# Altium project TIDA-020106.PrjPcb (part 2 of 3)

## Sheet CAN.SchDoc: CAN
size A4; Date: Not shown in title block; ApprovedBy: Hely Zhang; CheckedBy: Not shown in title block; Author: Not shown in title block; CompanyName: Not shown in title block; DrawnBy: Hely Zhang; Engineer: Not shown in title block; Organization: Not shown in title block; Address1: Not shown in title block; Address2: Not shown in title block; Address3: Not shown in title block; Address4: Not shown in title block; DocumentNumber: 1; Revision: Use project parameter SCH_Rev; SheetNumber: 8; SheetTotal: 15; PageSetup: Record=PageOptions¦CenterHorizontal=True¦CenterVertical=True¦PrintScale=0.93¦XCorrection=1.00¦YCorrection=1.00¦PrintKind=0¦BorderSize=5000000¦LeftOffset=0¦BottomOffset=0¦Orientation=2¦PaperLength=1000¦PaperWidth=1000¦Scale=100¦PaperSource=15¦PrintQuality=600¦MediaType=1¦DitherType=10¦PaperKind=Letter¦PrintScaleMode=1
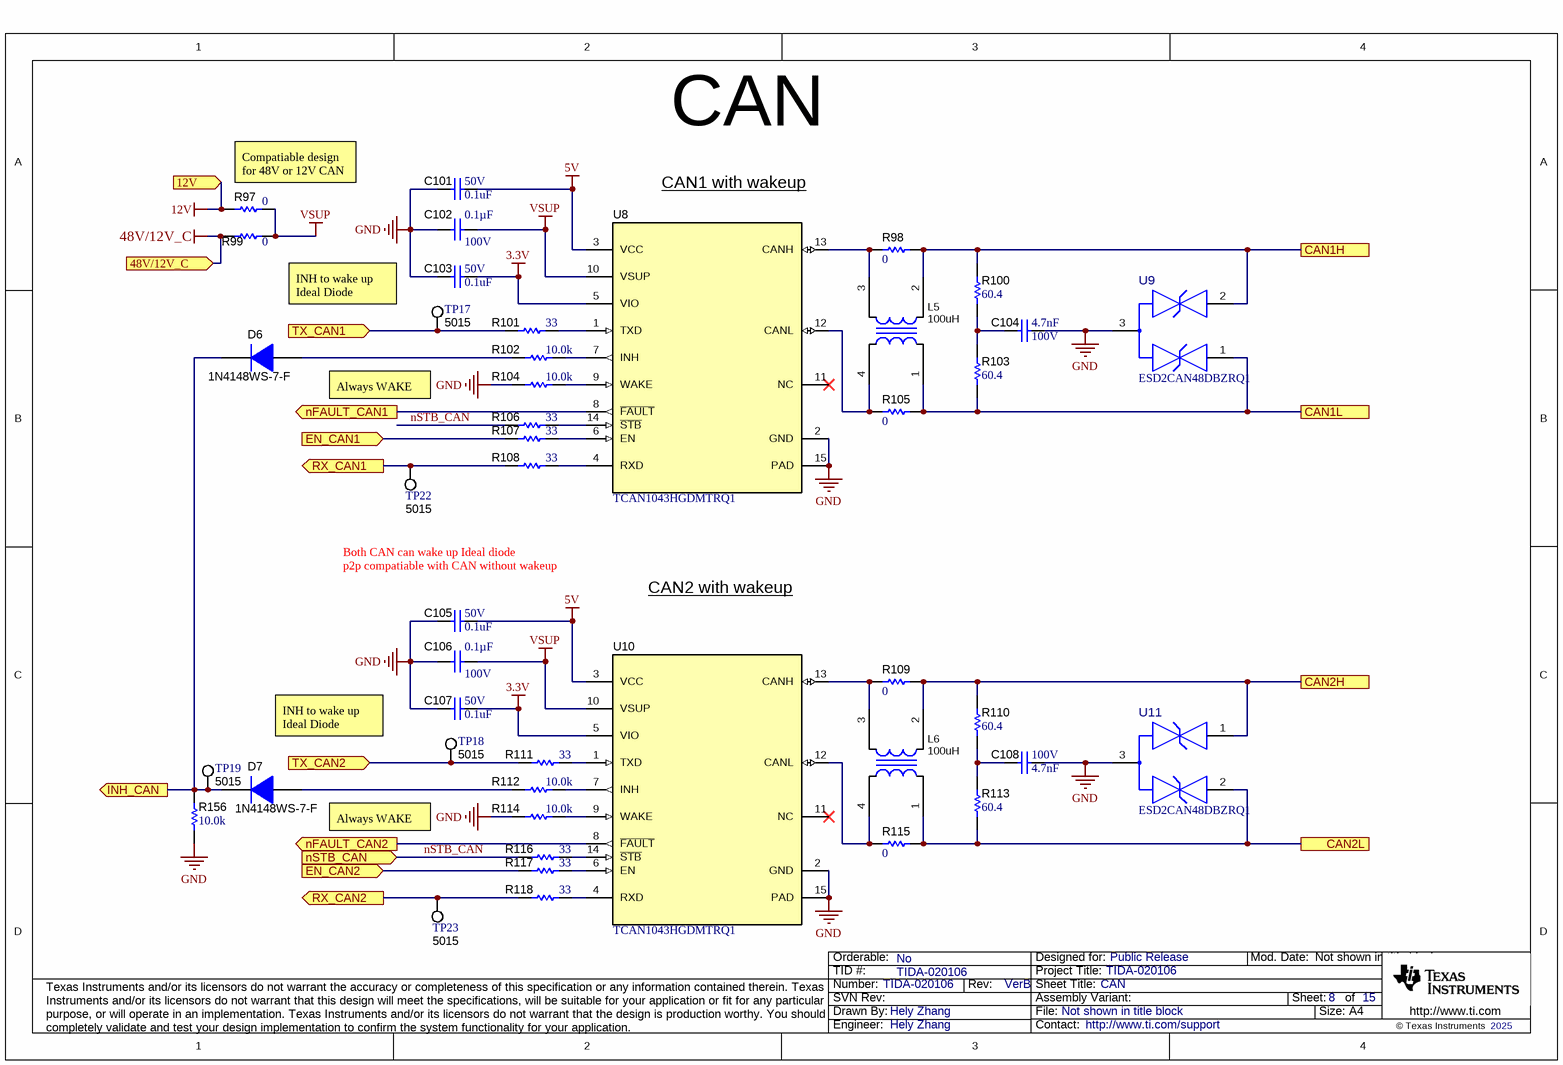
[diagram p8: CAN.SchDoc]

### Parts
C101  VDC_V: 50V  ValueDisplayed: 0.1uF  [0402]  (hidden comment: GCM155R71H104KE02D)
C102  ValueDisplayed: 0.1µF  VDC_V: 100V  [0603]  (hidden comment: GCJ188L8EL104KA07D)
C103  VDC_V: 50V  ValueDisplayed: 0.1uF  [0402]  (hidden comment: GCM155R71H104KE02D)
C104  Cap_F: 4.7nF  VDC_V: 100V  [0603]  (hidden comment: GCM188R72A472KA37D)
C105  VDC_V: 50V  ValueDisplayed: 0.1uF  [0402]  (hidden comment: GCM155R71H104KE02D)
C106  ValueDisplayed: 0.1µF  VDC_V: 100V  [0603]  (hidden comment: GCJ188L8EL104KA07D)
C107  VDC_V: 50V  ValueDisplayed: 0.1uF  [0402]  (hidden comment: GCM155R71H104KE02D)
C108  Cap_F: 4.7nF  VDC_V: 100V  [0603]  (hidden comment: GCM188R72A472KA37D)
D6  1N4148WS-7-F  [SOD-323]
D7  1N4148WS-7-F  [SOD-323]
L5  ValueDisplayed: 100uH  [ACT45B]  (hidden comment: ACT45B-101-2P-TL003)
L6  ValueDisplayed: 100uH  [ACT45B]  (hidden comment: ACT45B-101-2P-TL003)
R97  ValueDisplayed: 0  [0402]  (hidden comment: CRCW04020000Z0ED)
R98  ValueDisplayed: 0  [0402]  (hidden comment: CRCW04020000Z0ED)
R99  ValueDisplayed: 0  [0402]  (hidden comment: CRCW04020000Z0ED)
R100  ValueDisplayed: 60.4  [0402]  (hidden comment: CRCW040260R4FKED)
R101  ValueDisplayed: 33  [0402]  (hidden comment: CRCW040233R0JNED)
R102  ValueDisplayed: 10.0k  [0402]  (hidden comment: CRCW040210K0FKED)
R103  ValueDisplayed: 60.4  [0402]  (hidden comment: CRCW040260R4FKED)
R104  ValueDisplayed: 10.0k  [0402]  (hidden comment: CRCW040210K0FKED)
R105  ValueDisplayed: 0  [0402]  (hidden comment: CRCW04020000Z0ED)
R106  ValueDisplayed: 33  [0402]  (hidden comment: CRCW040233R0JNED)
R107  ValueDisplayed: 33  [0402]  (hidden comment: CRCW040233R0JNED)
R108  ValueDisplayed: 33  [0402]  (hidden comment: CRCW040233R0JNED)
R109  ValueDisplayed: 0  [0402]  (hidden comment: CRCW04020000Z0ED)
R110  ValueDisplayed: 60.4  [0402]  (hidden comment: CRCW040260R4FKED)
R111  ValueDisplayed: 33  [0402]  (hidden comment: CRCW040233R0JNED)
R112  ValueDisplayed: 10.0k  [0402]  (hidden comment: CRCW040210K0FKED)
R113  ValueDisplayed: 60.4  [0402]  (hidden comment: CRCW040260R4FKED)
R114  ValueDisplayed: 10.0k  [0402]  (hidden comment: CRCW040210K0FKED)
R115  ValueDisplayed: 0  [0402]  (hidden comment: CRCW04020000Z0ED)
R116  ValueDisplayed: 33  [0402]  (hidden comment: CRCW040233R0JNED)
R117  ValueDisplayed: 33  [0402]  (hidden comment: CRCW040233R0JNED)
R118  ValueDisplayed: 33  [0402]  (hidden comment: CRCW040233R0JNED)
R156  ValueDisplayed: 10.0k  [0402]  (hidden comment: CRCW040210K0FKED)
TP17  5015  [Testpoint_Keystone_Miniature]
TP18  5015  [Testpoint_Keystone_Miniature]
TP19  5015  [Testpoint_Keystone_Miniature]
TP22  5015  [Testpoint_Keystone_Miniature]
TP23  5015  [Testpoint_Keystone_Miniature]
U8  TCAN1043HGDMTRQ1  [DMT0014A]
U9  ESD2CAN48DBZRQ1  [DBZ0003A-MFG]
U10  TCAN1043HGDMTRQ1  [DMT0014A]
U11  ESD2CAN48DBZRQ1  [DBZ0003A-MFG]

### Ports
12V (in), 48V/12V_C (in), CAN1H, CAN1L, CAN2H, CAN2L, EN_CAN1 (in), EN_CAN2 (in), INH_CAN (out), nFAULT_CAN1 (out), nFAULT_CAN2 (out), nSTB_CAN (in), RX_CAN1 (out), RX_CAN2 (out), TX_CAN1 (in), TX_CAN2 (in)

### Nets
3.3V: C103.1 C107.1 U8.5(VIO) U10.5(VIO)
5V: C101.1 C105.1 U8.3(VCC) U10.3(VCC)
12V: R97.2 ; port 12V
48V/12V_C: R99.2 ; port 48V/12V_C
GND: C101.2 C102.2 C103.2 C104.1 C105.2 C106.2 C107.2 C108.1 R104.2 R114.2 R156.2 U8.2(GND) U8.15(PAD) U9.3(GND) U10.2(GND) U10.15(PAD) U11.3(GND)
VSUP: C102.1 C106.1 R97.1 R99.1 U8.10(VSUP) U10.10(VSUP)
CAN1H: L5.2 R98.1 R100.2 U9.2(2_IO) ; port CAN1H
CAN1L: L5.1 R103.1 R105.1 U9.1(1_IO) ; port CAN1L
CAN2H: L6.2 R109.1 R110.2 U11.1(1_IO) ; port CAN2H
CAN2L: L6.1 R113.1 R115.1 U11.2(2_IO) ; port CAN2L
EN_CAN1: R107.1 ; port EN_CAN1
EN_CAN2: R117.1 ; port EN_CAN2
INH_CAN: D6.1(K) D7.1(K) R156.1 TP19.1 ; port INH_CAN
nFAULT_CAN1: U8.8(~{FAULT}) ; port nFAULT_CAN1
nFAULT_CAN2: U10.8(~{FAULT}) ; port nFAULT_CAN2
nSTB_CAN: R106.1 R116.1 ; port nSTB_CAN
RX_CAN1: R108.1 TP22.1 ; port RX_CAN1
RX_CAN2: R118.1 TP23.1 ; port RX_CAN2
TX_CAN1: R101.1 TP17.1 ; port TX_CAN1
TX_CAN2: R111.1 TP18.1 ; port TX_CAN2
NetC104_2: C104.2 R100.1 R103.2
NetC108_2: C108.2 R110.1 R113.2
NetD6_2: D6.2(A) R102.2
NetD7_2: D7.2(A) R112.2
NetL5_3: L5.3 R98.2 U8.13(CANH)
NetL5_4: L5.4 R105.2 U8.12(CANL)
NetL6_3: L6.3 R109.2 U10.13(CANH)
NetL6_4: L6.4 R115.2 U10.12(CANL)
NetR101_2: R101.2 U8.1(TXD)
NetR102_1: R102.1 U8.7(INH)
NetR104_1: R104.1 U8.9(WAKE)
NetR106_2: R106.2 U8.14(~{STB})
NetR107_2: R107.2 U8.6(EN)
NetR108_2: R108.2 U8.4(RXD)
NetR111_2: R111.2 U10.1(TXD)
NetR112_1: R112.1 U10.7(INH)
NetR114_1: R114.1 U10.9(WAKE)
NetR116_2: R116.2 U10.14(~{STB})
NetR117_2: R117.2 U10.6(EN)
NetR118_2: R118.2 U10.4(RXD)

Not connected (* = marked no-connect by the designer): U8 11(NC)*; U10 11(NC)*

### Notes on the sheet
- CAN
- (near R97) Compatiable design for 48V or 12V CAN
- CAN1 with wakeup
- INH to wake up Ideal Diode
- Always WAKE
- Both CAN can wake up Ideal diode
- (near C105) p2p compatiable with CAN without wakeup
- CAN2 with wakeup

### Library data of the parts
C101 C103 C105 C107 = CMP-0006356-2: CAP, CERM, 0.1 uF, 50 V, +/- 10%, X7R, AEC-Q200 Grade 1, 0402; Manufacturer: MuRata; TaMin_C: -55°C; Polarized: N; SizeAreaWB_mm2: 3; Value1: Unknown; U/M: EA; Value: 0.1uF; TaMax_C: 125°C; SizeZ_mm: 0.6; SizeX_mm: 1; SizeY_mm: 0.5; AEC Qualified: Y; Cap_F: 100nF; AEC Category: Q200
C102 C106 = CMP-0860999-1: CAP, CERM, 0.1 µF, 100 V,+/- 10%, X8L, AEC-Q200 Grade 0, 0603; Manufacturer: MuRata; Cap_F: 100nF; TaMax_C: 150°C; SizeAreaWB_mm2: 4.68; SizeArea_mm2: 1.28; Value: 0.1uF; SizeZ_mm: 1; AEC Qualified: Y; SizeX_mm: 1.6; AEC Grade: 0; SizeY_mm: 0.8; U/M: EA; TaMin_C: -55°C; Polarized: N; AEC Category: Q200
C104 C108 = CMP-0079247-1: CAP, CERM, 4700 pF, 100 V,+/- 10%, X7R, AEC-Q200 Grade 1, 0603; Manufacturer: MuRata; SizeAreaWB_mm2: 4.68; SizeArea_mm2: 1.28; AEC Qualified: Y; AEC Category: Q200; Value: 4700pF; TaMax_C: 125°C; SizeZ_mm: 1; Polarized: N; TaMin_C: -55°C; SizeY_mm: 0.8; U/M: EA; SizeX_mm: 1.6
D6 D7 = CMP-0079597-2: Diode, Switching, 75 V, 0.15 A, AEC-Q101, SOD-323; Manufacturer: Diodes Inc.; SizeX_mm: 2.7; Vf_V: 1.25V; AEC Qualified: Y; SizeArea_mm2: 3.645; AEC Category: Q101; SizeAreaWB_mm2: 8.695; Io_A: 150mA; SizeZ_mm: 1; Value1: 0.15A; SizeY_mm: 1.35; TJmax_C: 150°C; Vr_V: 75V; Value: 75V
L5 L6 = CMP-0062430-2: Inductor, Ferrite, 100 uH, 0.15 A, 2 ohm, SMD; Manufacturer: TDK; Isat: 0.15A @ % inductance drop; Green_Lifecycle: Active; SizeAreaWB_mm2: 23.1; DCR_ohm: 2; Green_REACh: Passed; Value1: 2 ohm; Value: 100uH; Imax_A: 150mA; SizeZ_mm: 3; SizeX_mm: 4.5; SizeY_mm: 3.2; Value2: 0.15A; SizeArea_mm2: 14.4; Ind_H: 100µH; AEC Category: Q200
R97-R99 R105 R109 R115 = CMP-0026822-3: RES, 0, 5%, 0.063 W, AEC-Q200 Grade 0, 0402; Manufacturer: Vishay-Dale; Power_W: 63mW; TempCo: 200 ppm/C; Value_Code: 0000; Value: 0; EIA_Code: E24; SizeX_mm: 1; SizeY_mm: 0.5; SizeZ_mm: 0.6; Value2: 0.063W; AEC Qualified: Y; VDC_V: 50V; AEC Category: Q200
R100 R103 R110 R113 = CMP-0026487-2: RES, 60.4, 1%, 0.063 W, AEC-Q200 Grade 0, 0402; Manufacturer: Vishay-Dale; Power_W: 63mW; TempCo: 100 ppm/C; Value_Code: 60R4; Value: 60.4; EIA_Code: E96; SizeX_mm: 1; SizeY_mm: 0.5; SizeZ_mm: 0.6; Value2: 0.063W; AEC Qualified: Y; VDC_V: 50V; AEC Category: Q200; AEC Grade: 0
R101 R106-R108 R111 R116-R118 = CMP-0026908-3: RES, 33, 5%, 0.063 W, AEC-Q200 Grade 0, 0402; Manufacturer: Vishay-Dale; Power_W: 63mW; TempCo: 200 ppm/C; Value_Code: 33R0; Value: 33; EIA_Code: E24; SizeX_mm: 1; SizeY_mm: 0.5; SizeZ_mm: 0.6; Value2: 0.063W; AEC Qualified: Y; VDC_V: 50V; AEC Category: Q200; AEC Grade: 0
R102 R104 R112 R114 R156 = CMP-0025958-3: RES, 10.0 k, 1%, 0.063 W, AEC-Q200 Grade 0, 0402; Manufacturer: Vishay-Dale; Power_W: 63mW; TempCo: 100 ppm/C; Value_Code: 10k0; Value: 10.0k; EIA_Code: E96; Res_ohm: 10k; SizeX_mm: 1; SizeY_mm: 0.5; SizeZ_mm: 0.6; Value2: 0.063W; AEC Qualified: Y; VDC_V: 50V; AEC Category: Q200; AEC Grade: 0
TP17-TP19 TP22 TP23 = CMP-0055152-1: Test Point, Miniature, SMT; Manufacturer: Keystone; CNHeader: FALSE; Green_Lifecycle: Active; Green_REACh: Passed; CT: TRUE
U8 U10 = CMP-0013353-2: Fault Protected CAN Transceiver with CAN FD, DMT0014A (VSON-14); Manufacturer: Texas Instruments; Alternate PartNumber: TCAN1043HGDMTQ1; SizeX_mm: 3; SizeY_mm: 4.5; CompType: IC; SizeZ_mm: 0.9; SizeArea_mm2: 13.5; SizeAreaWB_mm2: 22; U/M: EA
U9 U11 = CMP-0127962-1: Automotive 2-Channel, 48V ESD Protection Diode for In-Vehicle Networks; Manufacturer: Texas Instruments; AEC Qualified: Yes; SizeZ_mm: 1.12mm; Ipp: 6A; Ppk: 500W; AEC Grade: Grade 0; Breakdown Voltage: 52V; Cap_F: 1.9pF; Clamping Voltage: 64V; Direction: Bidirectional; Number Of Channels: 2; Standoff Height: 0.01mm; TaMax_C: +150°C; TaMin_C: -55°C

## Sheet Sensor.SchDoc: Sensor
size A4; Date: Not shown in title block; ApprovedBy: Hely Zhang; CheckedBy: Not shown in title block; Author: Not shown in title block; CompanyName: Not shown in title block; DrawnBy: Hely Zhang; Engineer: Not shown in title block; Organization: Not shown in title block; Address1: Not shown in title block; Address2: Not shown in title block; Address3: Not shown in title block; Address4: Not shown in title block; DocumentNumber: 1; Revision: Use project parameter SCH_Rev; SheetNumber: 9; SheetTotal: 15; PageSetup: Record=PageOptions¦CenterHorizontal=True¦CenterVertical=True¦PrintScale=0.93¦XCorrection=1.00¦YCorrection=1.00¦PrintKind=0¦BorderSize=5000000¦LeftOffset=0¦BottomOffset=0¦Orientation=2¦PaperLength=1000¦PaperWidth=1000¦Scale=100¦PaperSource=15¦PrintQuality=600¦MediaType=1¦DitherType=10¦PaperKind=Letter¦PrintScaleMode=1
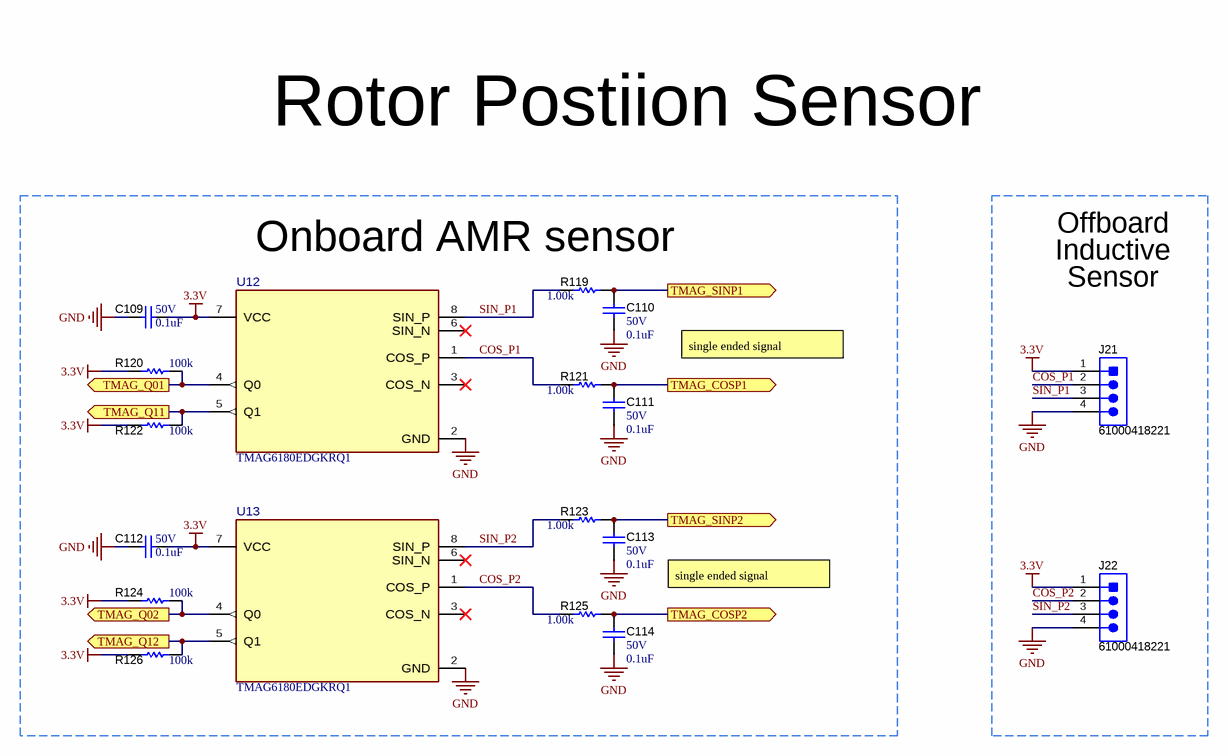
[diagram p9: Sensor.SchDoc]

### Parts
C109  VDC_V: 50V  ValueDisplayed: 0.1uF  [0402]  (hidden comment: GCM155R71H104KE02D)
C110  VDC_V: 50V  ValueDisplayed: 0.1uF  [0402]  (hidden comment: GCM155R71H104KE02D)
C111  VDC_V: 50V  ValueDisplayed: 0.1uF  [0402]  (hidden comment: GCM155R71H104KE02D)
C112  VDC_V: 50V  ValueDisplayed: 0.1uF  [0402]  (hidden comment: GCM155R71H104KE02D)
C113  VDC_V: 50V  ValueDisplayed: 0.1uF  [0402]  (hidden comment: GCM155R71H104KE02D)
C114  VDC_V: 50V  ValueDisplayed: 0.1uF  [0402]  (hidden comment: GCM155R71H104KE02D)
J21  61000418221  [Wurth_61000418221]
J22  61000418221  [Wurth_61000418221]
R119  ValueDisplayed: 1.00k  [0402]  (hidden comment: CRCW04021K00FKED)
R120  ValueDisplayed: 100k  [0402]  (hidden comment: CRCW0402100KFKED)
R121  ValueDisplayed: 1.00k  [0402]  (hidden comment: CRCW04021K00FKED)
R122  ValueDisplayed: 100k  [0402]  (hidden comment: CRCW0402100KFKED)
R123  ValueDisplayed: 1.00k  [0402]  (hidden comment: CRCW04021K00FKED)
R124  ValueDisplayed: 100k  [0402]  (hidden comment: CRCW0402100KFKED)
R125  ValueDisplayed: 1.00k  [0402]  (hidden comment: CRCW04021K00FKED)
R126  ValueDisplayed: 100k  [0402]  (hidden comment: CRCW0402100KFKED)
U12  TMAG6180EDGKRQ1  [DGK0008A-MFG]
U13  TMAG6180EDGKRQ1  [DGK0008A-MFG]

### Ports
TMAG_COSP1 (out), TMAG_COSP2 (out), TMAG_Q01 (out), TMAG_Q02 (out), TMAG_Q11 (out), TMAG_Q12 (out), TMAG_SINP1 (out), TMAG_SINP2 (out)

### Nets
3.3V: C109.1 C112.1 J21.1 J22.1 R120.1 R122.1 R124.1 R126.1 U12.7(VCC) U13.7(VCC)
GND: C109.2 C110.2 C111.2 C112.2 C113.2 C114.2 J21.4 J22.4 U12.2(GND) U13.2(GND)
COS_P1: J21.2 R121.1 U12.1(COS_P)
COS_P2: J22.2 R125.1 U13.1(COS_P)
SIN_P1: J21.3 R119.1 U12.8(SIN_P)
SIN_P2: J22.3 R123.1 U13.8(SIN_P)
TMAG_COSP1: C111.1 R121.2 ; port TMAG_COSP1
TMAG_COSP2: C114.1 R125.2 ; port TMAG_COSP2
TMAG_Q01: R120.2 U12.4(Q0) ; port TMAG_Q01
TMAG_Q02: R124.2 U13.4(Q0) ; port TMAG_Q02
TMAG_Q11: R122.2 U12.5(Q1) ; port TMAG_Q11
TMAG_Q12: R126.2 U13.5(Q1) ; port TMAG_Q12
TMAG_SINP1: C110.1 R119.2 ; port TMAG_SINP1
TMAG_SINP2: C113.1 R123.2 ; port TMAG_SINP2

Not connected (* = marked no-connect by the designer): U12 3(COS_N)* 6(SIN_N)*; U13 3(COS_N)* 6(SIN_N)*

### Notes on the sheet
- Rotor Postiion Sensor
- Onboard AMR sensor
- Offboard
- Inductive
- Sensor
- single ended signal

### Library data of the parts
C109-C114 = CMP-0006356-2: as C101 on sheet CAN
J21 J22 = CMP-0054788-1: Header, 2.54mm, 4x1, Gold, SMT; Manufacturer: Wurth Elektronik; CNHeader: TRUE; Shrouded: N; Gender: Male; Row_Count: 1; Pitch_mm: 2.54; CT: FALSE
R119 R121 R123 R125 = CMP-0026071-3: RES, 1.00 k, 1%, 0.063 W, AEC-Q200 Grade 0, 0402; Manufacturer: Vishay-Dale; Power_W: 63mW; TempCo: 100 ppm/C; Value_Code: 1k00; Value: 1.00k; EIA_Code: E96; Res_ohm: 1k; SizeX_mm: 1; SizeY_mm: 0.5; SizeZ_mm: 0.6; Value2: 0.063W; AEC Qualified: Y; VDC_V: 50V; AEC Category: Q200; AEC Grade: 0
R120 R122 R124 R126 = CMP-0025950-3: RES, 100 k, 1%, 0.063 W, AEC-Q200 Grade 0, 0402; Manufacturer: Vishay-Dale; Power_W: 63mW; TempCo: 100 ppm/C; Value: 100k; EIA_Code: E96; SizeX_mm: 1; SizeY_mm: 0.5; SizeZ_mm: 0.6; Value2: 0.063W; AEC Qualified: Y; VDC_V: 50V; AEC Category: Q200; AEC Grade: 0
U12 U13 = CMP-0095386-1: Hall Effect Magnetic Sensor VSSOP8; Manufacturer: Texas Instruments; SizeZ_mm: 1.1mm; Standoff Height: 0.05mm; AEC Grade: Grade 0; Max Supply Voltage: 5.5V; Min Supply Voltage: 2.7V; AEC Qualified: Yes

## Sheet PMIC.SchDoc: PMIC
size A4; Date: Not shown in title block; ApprovedBy: Not shown in title block; CheckedBy: Not shown in title block; Author: Not shown in title block; CompanyName: Not shown in title block; DrawnBy: Hely Zhang; Engineer: Not shown in title block; Organization: Not shown in title block; Address1: Not shown in title block; Address2: Not shown in title block; Address3: Not shown in title block; Address4: Not shown in title block; DocumentNumber: 6; Revision: Use project parameter SCH_Rev; SheetNumber: 5; SheetTotal: 15; PageSetup: Record=PageOptions¦CenterHorizontal=True¦CenterVertical=True¦PrintScale=1.00¦XCorrection=1.00¦YCorrection=1.00¦PrintKind=0¦BorderSize=5000000¦LeftOffset=0¦BottomOffset=0¦Orientation=2¦PaperLength=1000¦PaperWidth=1000¦Scale=100¦PaperSource=15¦PrintQuality=600¦MediaType=1¦DitherType=10¦PaperKind=Letter¦PrintScaleMode=1
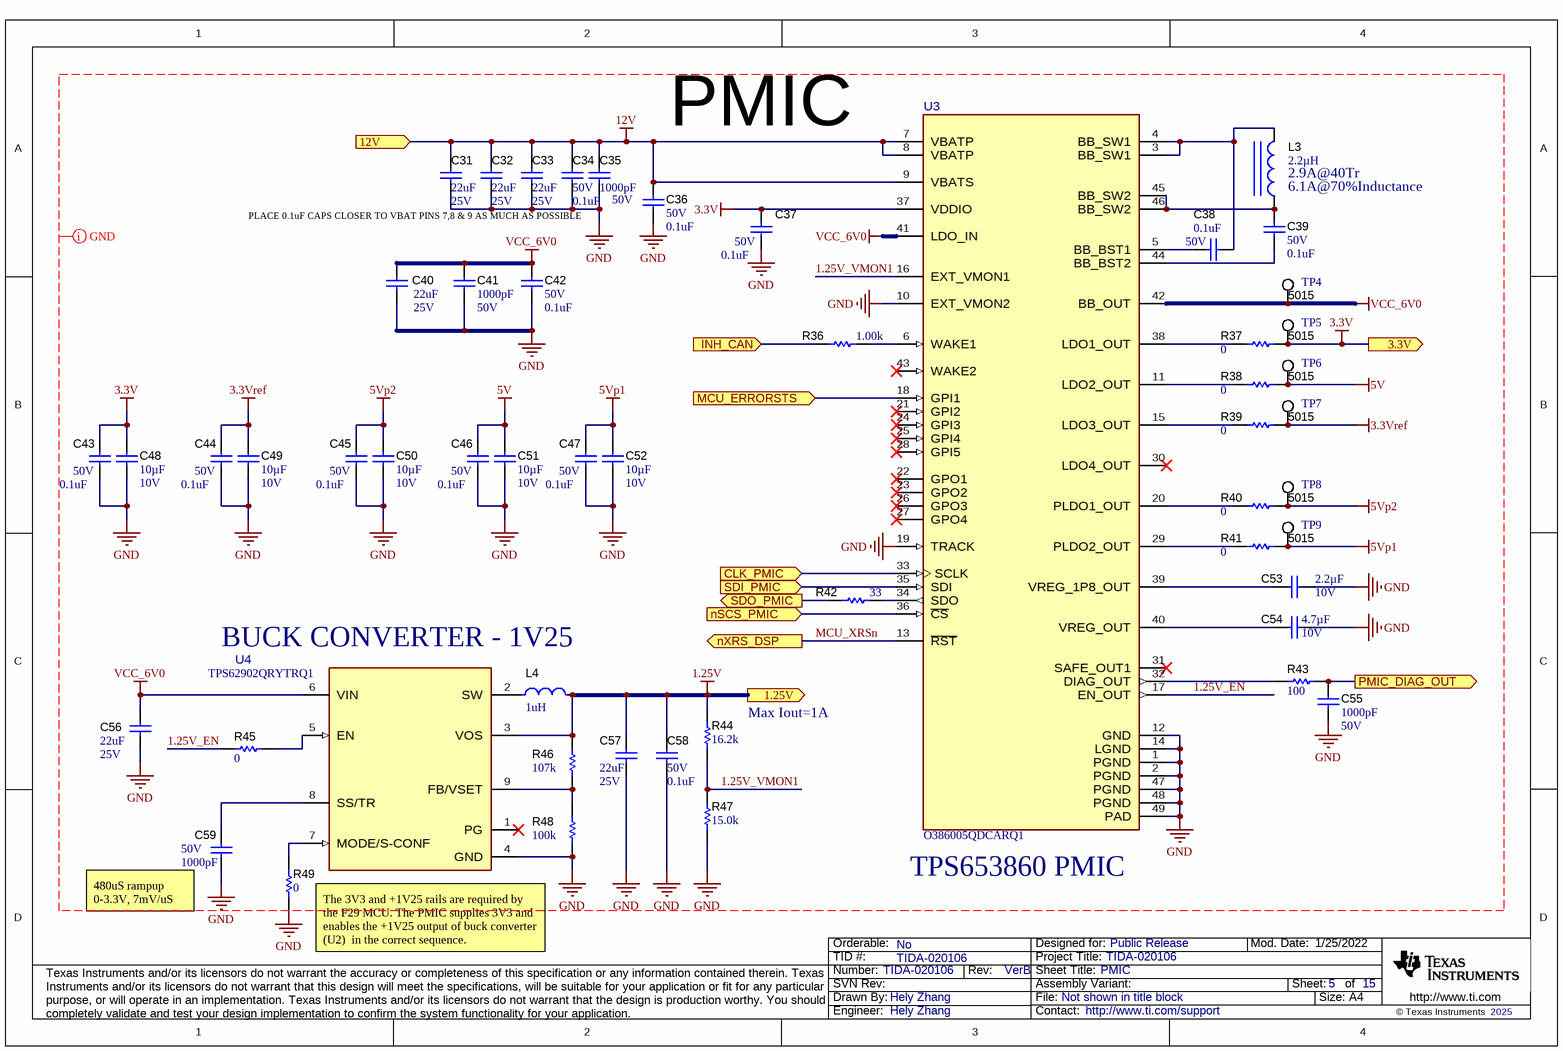
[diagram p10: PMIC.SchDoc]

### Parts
C31  VDC_V: 25V  ValueDisplayed: 22uF  [0805_HV]  (hidden comment: GRM21BR61E226ME44L)
C32  VDC_V: 25V  ValueDisplayed: 22uF  [0805_HV]  (hidden comment: GRM21BR61E226ME44L)
C33  VDC_V: 25V  ValueDisplayed: 22uF  [0805_HV]  (hidden comment: GRM21BR61E226ME44L)
C34  VDC_V: 50V  ValueDisplayed: 0.1uF  [0402]  (hidden comment: GCM155R71H104KE02D)
C35  ValueDisplayed: 1000pF  VDC_V: 50V  [0402]  (hidden comment: CGA2B2X8R1H102K050BA)
C36  VDC_V: 50V  ValueDisplayed: 0.1uF  [0402]  (hidden comment: GCM155R71H104KE02D)
C37  VDC_V: 50V  ValueDisplayed: 0.1uF  [0402]  (hidden comment: GCM155R71H104KE02D)
C38  VDC_V: 50V  ValueDisplayed: 0.1uF  [0402]  (hidden comment: GCM155R71H104KE02D)
C39  VDC_V: 50V  ValueDisplayed: 0.1uF  [0402]  (hidden comment: GCM155R71H104KE02D)
C40  VDC_V: 25V  ValueDisplayed: 22uF  [0805_HV]  (hidden comment: GRM21BR61E226ME44L)
C41  ValueDisplayed: 1000pF  VDC_V: 50V  [0402]  (hidden comment: CGA2B2X8R1H102K050BA)
C42  VDC_V: 50V  ValueDisplayed: 0.1uF  [0402]  (hidden comment: GCM155R71H104KE02D)
C43  VDC_V: 50V  ValueDisplayed: 0.1uF  [0402]  (hidden comment: GCM155R71H104KE02D)
C44  VDC_V: 50V  ValueDisplayed: 0.1uF  [0402]  (hidden comment: GCM155R71H104KE02D)
C45  VDC_V: 50V  ValueDisplayed: 0.1uF  [0402]  (hidden comment: GCM155R71H104KE02D)
C46  VDC_V: 50V  ValueDisplayed: 0.1uF  [0402]  (hidden comment: GCM155R71H104KE02D)
C47  VDC_V: 50V  ValueDisplayed: 0.1uF  [0402]  (hidden comment: GCM155R71H104KE02D)
C48  Cap_F: 10µF  VDC_V: 10V  [0603]  (hidden comment: GRM188Z71A106MA73D)
C49  Cap_F: 10µF  VDC_V: 10V  [0603]  (hidden comment: GRM188Z71A106MA73D)
C50  Cap_F: 10µF  VDC_V: 10V  [0603]  (hidden comment: GRM188Z71A106MA73D)
C51  Cap_F: 10µF  VDC_V: 10V  [0603]  (hidden comment: GRM188Z71A106MA73D)
C52  Cap_F: 10µF  VDC_V: 10V  [0603]  (hidden comment: GRM188Z71A106MA73D)
C53  Cap_F: 2.2µF  VDC_V: 10V  [0603]  (hidden comment: GRM188R71A225KE15J)
C54  Cap_F: 4.7µF  VDC_V: 10V  [0603]  (hidden comment: GRM188Z71A475ME15D)
C55  ValueDisplayed: 1000pF  VDC_V: 50V  [0402]  (hidden comment: CGA2B2X8R1H102K050BA)
C56  VDC_V: 25V  ValueDisplayed: 22uF  [0805_HV]  (hidden comment: GRM21BR61E226ME44L)
C57  VDC_V: 25V  ValueDisplayed: 22uF  [0805_HV]  (hidden comment: GRM21BR61E226ME44L)
C58  VDC_V: 50V  ValueDisplayed: 0.1uF  [0402]  (hidden comment: GCM155R71H104KE02D)
C59  ValueDisplayed: 1000pF  VDC_V: 50V  [0402]  (hidden comment: CGA2B2X8R1H102K050BA)
L3  ValueDisplayed: 2.2µH  [WE-MAPI_3012]  (hidden comment: 74438334022)
L4  value 1uH  [FP-XGL4030-102MEC_SMD_IND_4MM0_4MM0-MFG]  (hidden comment: XGL4030-102MEC)
R36  ValueDisplayed: 1.00k  [0402]  (hidden comment: CRCW04021K00FKED)
R37  ValueDisplayed: 0  [0402]  (hidden comment: CRCW04020000Z0ED)
R38  ValueDisplayed: 0  [0402]  (hidden comment: CRCW04020000Z0ED)
R39  ValueDisplayed: 0  [0402]  (hidden comment: CRCW04020000Z0ED)
R40  ValueDisplayed: 0  [0402]  (hidden comment: CRCW04020000Z0ED)
R41  ValueDisplayed: 0  [0402]  (hidden comment: CRCW04020000Z0ED)
R42  ValueDisplayed: 33  [0402]  (hidden comment: CRCW040233R0JNED)
R43  ValueDisplayed: 100  [0402]  (hidden comment: CRCW0402100RFKED)
R44  ValueDisplayed: 16.2k  [0402]  (hidden comment: CRCW040216K2FKED)
R45  ValueDisplayed: 0  [0402]  (hidden comment: CRCW04020000Z0ED)
R46  ValueDisplayed: 107k  [0402]  (hidden comment: CRCW0402107KFKED)
R47  ValueDisplayed: 15.0k  [0402]  (hidden comment: CRCW040215K0FKED)
R48  ValueDisplayed: 100k  [0402]  (hidden comment: CRCW0402100KFKED)
R49  ValueDisplayed: 0  [0402]  (hidden comment: CRCW04020000Z0ED)
TP4  5015  [Testpoint_Keystone_Miniature]
TP5  5015  [Testpoint_Keystone_Miniature]
TP6  5015  [Testpoint_Keystone_Miniature]
TP7  5015  [Testpoint_Keystone_Miniature]
TP8  5015  [Testpoint_Keystone_Miniature]
TP9  5015  [Testpoint_Keystone_Miniature]
U3  O386005QDCARQ1  [DCA0048J-MFG]
U4  TPS62902QRYTRQ1  [RYT0009A-MFG]

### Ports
1.25V (out), 3.3V (out), 12V (in), CLK_PMIC (in), INH_CAN (in), MCU_ERRORSTS (in), nSCS_PMIC (in), nXRS_DSP (out), PMIC_DIAG_OUT (out), SDI_PMIC (in), SDO_PMIC (out)

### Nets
1.25V: C57.1 C58.2 L4.2 R44.2 R46.2 U4.3(VOS) ; port 1.25V
3.3V: C37.2 C43.2 C48.1 R37.1 TP5.1 U3.37(VDDIO) ; port 3.3V
3.3Vref: C44.2 C49.1 R39.1 TP7.1
5V: C46.2 C51.1 R38.1 TP6.1
5Vp1: C47.2 C52.1 R41.1 TP9.1
5Vp2: C45.2 C50.1 R40.1 TP8.1
12V: C31.1 C32.1 C33.1 C34.1 C35.1 C36.1 U3.7(VBATP) U3.8(VBATP) U3.9(VBATS) ; port 12V
GND: C31.2 C32.2 C33.2 C34.2 C35.2 C36.2 C37.1 C40.2 C41.2 C42.2 C43.1 C44.1 C45.1 C46.1 C47.1 C48.2 C49.2 C50.2 C51.2 C52.2 C53.1 C54.1 C55.2 C56.2 C57.2 C58.1 C59.1 R47.1 R48.2 R49.1 U3.1(PGND) U3.2(PGND) U3.10(EXT_VMON2) U3.12(GND) U3.14(LGND) U3.19(TRACK) U3.47(PGND) U3.48(PGND) U3.49(PAD) U4.4(GND)
VCC_6V0: C40.1 C41.1 C42.1 C56.1 TP4.1 U3.41(LDO_IN) U3.42(BB_OUT) U4.6(VIN)
1.25V_EN: R45.2 U3.17(EN_OUT)
1.25V_VMON1: R44.1 R47.2 U3.16(EXT_VMON1)
CLK_PMIC: U3.33(SCLK) ; port CLK_PMIC
INH_CAN: R36.1 ; port INH_CAN
MCU_ERRORSTS: U3.18(GPI1) ; port MCU_ERRORSTS
nSCS_PMIC: U3.36(~{CS}) ; port nSCS_PMIC
nXRS_DSP: U3.13(~{RST}) ; port nXRS_DSP
PMIC_DIAG_OUT: C55.1 R43.2 ; port PMIC_DIAG_OUT
SDI_PMIC: U3.35(SDI) ; port SDI_PMIC
SDO_PMIC: R42.1 ; port SDO_PMIC
NetC38_1: C38.1 L3.2 U3.3(BB_SW1) U3.4(BB_SW1)
NetC38_2: C38.2 U3.5(BB_BST1)
NetC39_1: C39.1 L3.1 U3.45(BB_SW2) U3.46(BB_SW2)
NetC39_2: C39.2 U3.44(BB_BST2)
NetC53_2: C53.2 U3.39(VREG_1P8_OUT)
NetC54_2: C54.2 U3.40(VREG_OUT)
NetC59_2: C59.2 U4.8(SS/TR)
NetL4_1: L4.1 U4.2(SW)
NetR36_2: R36.2 U3.6(WAKE1)
NetR37_2: R37.2 U3.38(LDO1_OUT)
NetR38_2: R38.2 U3.11(LDO2_OUT)
NetR39_2: R39.2 U3.15(LDO3_OUT)
NetR40_2: R40.2 U3.20(PLDO1_OUT)
NetR41_2: R41.2 U3.29(PLDO2_OUT)
NetR42_2: R42.2 U3.34(SDO)
NetR43_1: R43.1 U3.32(DIAG_OUT)
NetR45_1: R45.1 U4.5(EN)
NetR46_1: R46.1 R48.1 U4.9(FB/VSET)
NetR49_2: R49.2 U4.7(MODE/S-CONF)

Not connected (* = marked no-connect by the designer): U3 21(GPI2)* 22(GPO1)* 23(GPO2)* 24(GPI3)* 25(GPI4)* 26(GPO3)* 27(GPO4)* 28(GPI5)* 30(LDO4_OUT)* 31(SAFE_OUT1)* 43(WAKE2)*; U4 1(PG)*

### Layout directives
net class GND: 1.25V, 1.25V_EN, 1.25V_VMON1, 3.3V, 3.3Vref, 5V, 5Vp1, 5Vp2, 12V, GND, VCC_6V0

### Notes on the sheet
- PMIC
- (near L3) 2.9A@40Tr
- (near L3) 6.1A@70%Inductance
- PLACE 0.1uF CAPS CLOSER TO VBAT PINS 7,8 & 9 AS MUCH AS POSSIBLE
- BUCK CONVERTER - 1V25
- (near R42) MCU_XRSn
- (near R44) Max Iout=1A
- (near C59) 480uS rampup 0-3.3V, 7mV/uS
- (near U3) TPS653860 PMIC
- The 3V3 and +1V25 rails are required by the F29 MCU. The PMIC supplies 3V3 and enables the +1V25 output of buck converter (U2)  in the correct sequence.

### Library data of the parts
C31-C33 = CMP-0008305-2: CAP, CERM, 22 uF, 25 V, +/- 20%, X5R, 0805; Manufacturer: MuRata; TaMin_C: -55°C; Polarized: N; SizeAreaWB_mm2: 6.75; Value1: Unknown; U/M: EA; Value: 22uF; TaMax_C: 85°C; SizeZ_mm: 1.45; SizeX_mm: 2; SizeY_mm: 1.25; Cap_Case: 0805; SizeArea_mm2: 2.5; Cap_F: 22µF; AEC Category: Q200
C34 C36-C39 C42-C47 C58 = CMP-0006356-2: as C101 on sheet CAN
C35 C41 C55 C59 = CMP-0860997-1: CAP, CERM, 1000 pF, 50 V,+/- 10%, X8R, AEC-Q200 Grade 0, 0402; Manufacturer: TDK; SizeArea_mm2: 0.5; U/M: EA; SizeX_mm: 1; Polarized: N; AEC Grade: 0; AEC Qualified: Y; TaMin_C: -55°C; Value: 1000pF; TaMax_C: 150°C; SizeZ_mm: 0.6; Cap_F: 1nF; SizeAreaWB_mm2: 3; AEC Category: Q200
C40 C56 C57 = CMP-0008305-2: CAP, CERM, 22 uF, 25 V, +/- 20%, X5R, 0805; Manufacturer: MuRata; SizeZ_mm: 1.45; AEC Qualified: N; Value: 22uF; Cap_F: 22µF; AEC Category: Q200; Cap_Case: 0805; SizeArea_mm2: 2.5; SizeAreaWB_mm2: 6.75; SizeX_mm: 2; SizeY_mm: 1.25; TaMax_C: 85°C; TaMin_C: -55°C; U/M: EA; Value1: Unknown
C48-C52 = CMP-0007497-1: CAP, CERM, 10 uF, 10 V, +/- 20%, X7R, 0603; Manufacturer: MuRata; TaMin_C: -55°C; Polarized: N; SizeAreaWB_mm2: 4.68; Value1: Unknown; U/M: EA; Value: 10uF; TaMax_C: 125°C; SizeZ_mm: 1; SizeX_mm: 1.6; SizeY_mm: 0.8; SizeArea_mm2: 1.28; AEC Category: Q200
C53 = CMP-0084284-1: CAP, CERM, 2.2 µF, 10 V,+/- 10%, X7R, AEC-Q200 Grade 1, 0603; Manufacturer: MuRata; SizeAreaWB_mm2: 4.68; Polarized: N; AEC Qualified: Y; SizeX_mm: 1.6; SizeZ_mm: 1; SizeY_mm: 0.8; U/M: EA; TaMin_C: -55°C; Value: 2.2uF; AEC Category: Q200; TaMax_C: 125°C; SizeArea_mm2: 1.28
C54 = CMP-0007498-2: CAP, CERM, 4.7 uF, 10 V, +/- 20%, X7R, 0603; Manufacturer: MuRata; TaMin_C: -55°C; Polarized: N; SizeAreaWB_mm2: 4.68; Value1: Unknown; U/M: EA; Value: 4.7uF; TaMax_C: 125°C; SizeZ_mm: 1; SizeX_mm: 1.6; SizeY_mm: 0.8; SizeArea_mm2: 1.28; AEC Category: Q200
L3 = CMP-0084500-1: Inductor, Shielded, Metal Composite, 2.2 µH, 1.8 A, 0.115 ohm, SMD; Manufacturer: Wurth Elektronik; Value: 2.2uH; SizeY_mm: 3; AEC Qualified: N; DCR_ohm: 0.115; Value2: 1.8A; Isat: 5A @ 20% inductance drop; SizeZ_mm: 1.2; SizeAreaWB_mm2: 16; Irms: 1.8A @ 40C rise; AEC Category: Q200; SizeArea_mm2: 9
L4 = CMP-0090842-1: Power Inductor, shielded, composite, 1uH 20% tol, DCR 7.2mOhms, SRF 65MHz, Isat 4.8A, Irms 13A, AEC-Q200; Manufacturer: Coilcraft; TaMin_C: -40°C; TaMax_C: +125°C; Test Frequency: 1MHz; DCR_ohm: 7.2m; AEC Grade: Grade 1; SizeZ_mm: 3.1mm; AEC Qualified: Yes; Shrouded: true; Ind_H: 1µH
R36 = CMP-0026071-3: as R119 on sheet Sensor
R37-R41 R45 R49 = CMP-0026822-3: as R97-R99 on sheet CAN
R42 = CMP-0026908-3: as R101 on sheet CAN
R43 = CMP-0025951-3: RES, 100, 1%, 0.063 W, AEC-Q200 Grade 0, 0402; Manufacturer: Vishay-Dale; Power_W: 63mW; TempCo: 100 ppm/C; Value_Code: 100R; Value: 100; EIA_Code: E96; SizeX_mm: 1; SizeY_mm: 0.5; SizeZ_mm: 0.6; Value2: 0.063W; AEC Qualified: Y; VDC_V: 50V; AEC Category: Q200; AEC Grade: 0
R44 = CMP-0026040-3: RES, 16.2 k, 1%, 0.063 W, AEC-Q200 Grade 0, 0402; Manufacturer: Vishay-Dale; Power_W: 63mW; TempCo: 100 ppm/C; Value_Code: 16k2; Value: 16.2k; EIA_Code: E96; SizeX_mm: 1; SizeY_mm: 0.5; SizeZ_mm: 0.6; Value2: 0.063W; AEC Qualified: Y; VDC_V: 50V; AEC Category: Q200; AEC Grade: 0
R46 = CMP-0025956-3: RES, 107 k, 1%, 0.063 W, AEC-Q200 Grade 0, 0402; Manufacturer: Vishay-Dale; Power_W: 63mW; TempCo: 100 ppm/C; Value: 107k; EIA_Code: E96; SizeX_mm: 1; SizeY_mm: 0.5; SizeZ_mm: 0.6; Value2: 0.063W; AEC Qualified: Y; VDC_V: 50V; AEC Category: Q200; AEC Grade: 0
R47 = CMP-0026027-3: RES, 15.0 k, 1%, 0.063 W, AEC-Q200 Grade 0, 0402; Manufacturer: Vishay-Dale; Power_W: 63mW; TempCo: 100 ppm/C; Value_Code: 15k0; Value: 15.0k; EIA_Code: E96; Res_ohm: 15k; SizeX_mm: 1; SizeY_mm: 0.5; SizeZ_mm: 0.6; Value2: 0.063W; AEC Qualified: Y; VDC_V: 50V; AEC Category: Q200; AEC Grade: 0
R48 = CMP-0025950-3: as R120 on sheet Sensor
TP4-TP9 = CMP-0055152-1: as TP17-TP19 on sheet CAN
U3 = CMP-0095884-2: Power Management IC For Safety-Relevant Applications HTSSOP48 5 Outputs 4 LDO and 1 Synchronous Buck-Boost Regulator; Manufacturer: Texas Instruments; SizeZ_mm: 1.2mm; AEC Qualified: Yes; Standoff Height: 0.05mm; Max Supply Voltage: 28V; TaMin_C: -40°C; AEC Grade: Grade 1; TJmax_C: +150°C; Min Supply Voltage: 2.3V; Number Of Outputs: 7; TaMax_C: +125°C; AEC Category: Q200
U4 = CMP-0121948-1: 3-V to 18-V, 2-A, Automotive Low IQ Buck Converter with +165°C TJ; Manufacturer: Texas Instruments; SizeZ_mm: 1.05mm; AEC Qualified: Yes; AEC Grade: Grade 1; Max Duty Cycle: 100%; Max Supply Voltage: 18V; Min Supply Voltage: 3V; Nominal Supply Current: 8mA; Number Of Outputs: 1; Output Type: AdjustableProgrammable; Output Voltage: 0.4-5.5V; Standoff Height: 0mm; Switching Frequency: 1/2.5MHz; TaMax_C: +125°C; TaMin_C: -40°C

## Sheet EPB.SchDoc: EPB & WSS
size A4; Date: Not shown in title block; ApprovedBy: Hely Zhang; CheckedBy: Not shown in title block; Author: Not shown in title block; CompanyName: Not shown in title block; DrawnBy: Hely Zhang; Engineer: Not shown in title block; Organization: Not shown in title block; Address1: Not shown in title block; Address2: Not shown in title block; Address3: Not shown in title block; Address4: Not shown in title block; DocumentNumber: 1; Revision: Use project parameter SCH_Rev; SheetNumber: 7; SheetTotal: 15; PageSetup: Record=PageOptions¦CenterHorizontal=True¦CenterVertical=True¦PrintScale=0.93¦XCorrection=1.00¦YCorrection=1.00¦PrintKind=0¦BorderSize=5000000¦LeftOffset=0¦BottomOffset=0¦Orientation=2¦PaperLength=1000¦PaperWidth=1000¦Scale=100¦PaperSource=15¦PrintQuality=600¦MediaType=1¦DitherType=10¦PaperKind=Letter¦PrintScaleMode=1
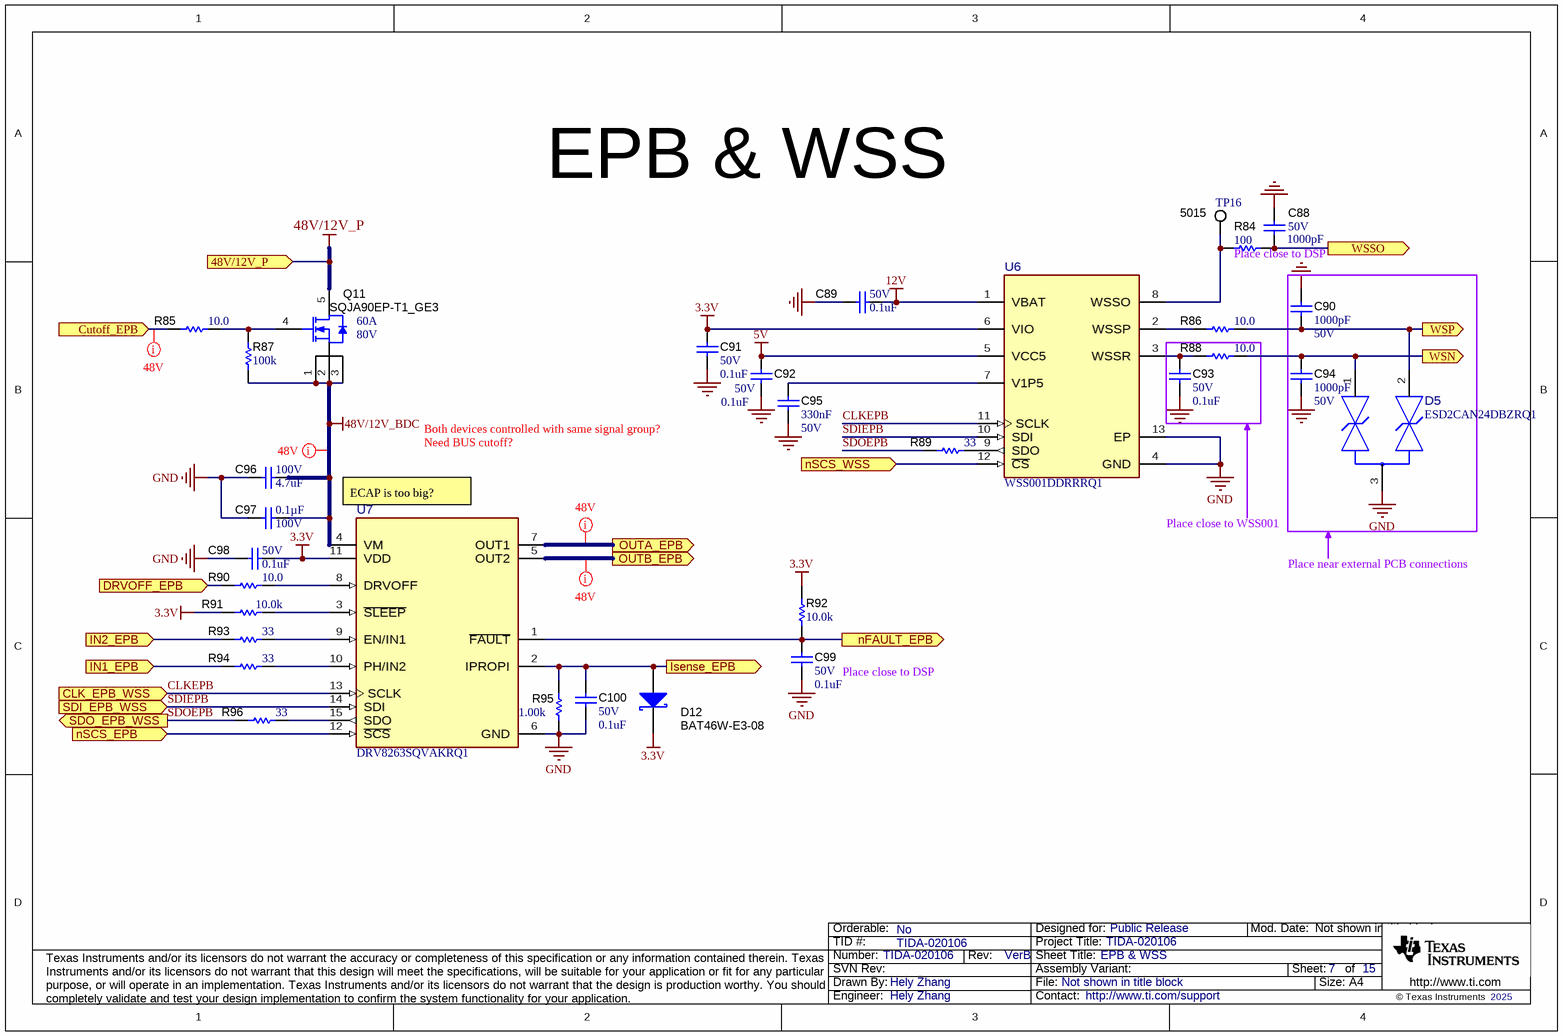
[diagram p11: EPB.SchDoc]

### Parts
C88  ValueDisplayed: 1000pF  VDC_V: 50V  [0402]  (hidden comment: CGA2B2X8R1H102K050BA)
C89  VDC_V: 50V  ValueDisplayed: 0.1uF  [0402]  (hidden comment: GCM155R71H104KE02D)
C90  ValueDisplayed: 1000pF  VDC_V: 50V  [0402]  (hidden comment: CGA2B2X8R1H102K050BA)
C91  VDC_V: 50V  ValueDisplayed: 0.1uF  [0402]  (hidden comment: GCM155R71H104KE02D)
C92  VDC_V: 50V  ValueDisplayed: 0.1uF  [0402]  (hidden comment: GCM155R71H104KE02D)
C93  VDC_V: 50V  ValueDisplayed: 0.1uF  [0402]  (hidden comment: GCM155R71H104KE02D)
C94  ValueDisplayed: 1000pF  VDC_V: 50V  [0402]  (hidden comment: CGA2B2X8R1H102K050BA)
C95  Cap_F: 330nF  VDC_V: 50V  [0603]  (hidden comment: CGA3E3X7R1H334K080AB)
C96  VDC_V: 100V  ValueDisplayed: 4.7uF  [1210_220]  (hidden comment: GRM32DC72A475KE01L)
C97  ValueDisplayed: 0.1µF  VDC_V: 100V  [0603]  (hidden comment: GCJ188L8EL104KA07D)
C98  VDC_V: 50V  ValueDisplayed: 0.1uF  [0402]  (hidden comment: GCM155R71H104KE02D)
C99  VDC_V: 50V  ValueDisplayed: 0.1uF  [0402]  (hidden comment: GCM155R71H104KE02D)
C100  VDC_V: 50V  ValueDisplayed: 0.1uF  [0402]  (hidden comment: GCM155R71H104KE02D)
D5  ESD2CAN24DBZRQ1  [DBZ0003A-MFG]
D12  BAT46W-E3-08  [SOD-123]
Q11  SQJA90EP-T1_GE3  value 80V  IdsMax_A: 60A  [PowerPAK_SO-8L]
R84  ValueDisplayed: 100  [0402]  (hidden comment: CRCW0402100RFKED)
R85  ValueDisplayed: 10.0  [0402]  (hidden comment: CRCW040210R0FKED)
R86  ValueDisplayed: 10.0  [0402]  (hidden comment: CRCW040210R0FKED)
R87  ValueDisplayed: 100k  [0402]  (hidden comment: CRCW0402100KFKED)
R88  ValueDisplayed: 10.0  [0402]  (hidden comment: CRCW040210R0FKED)
R89  ValueDisplayed: 33  [0402]  (hidden comment: CRCW040233R0JNED)
R90  ValueDisplayed: 10.0  [0402]  (hidden comment: CRCW040210R0FKED)
R91  ValueDisplayed: 10.0k  [0402]  (hidden comment: CRCW040210K0FKED)
R92  ValueDisplayed: 10.0k  [0402]  (hidden comment: CRCW040210K0FKED)
R93  ValueDisplayed: 33  [0402]  (hidden comment: CRCW040233R0JNED)
R94  ValueDisplayed: 33  [0402]  (hidden comment: CRCW040233R0JNED)
R95  ValueDisplayed: 1.00k  [0402]  (hidden comment: CRCW04021K00FKED)
R96  ValueDisplayed: 33  [0402]  (hidden comment: CRCW040233R0JNED)
TP16  5015  [Testpoint_Keystone_Miniature]
U6  WSS001DDRRRQ1  [DRR0012E-MFG]
U7  DRV8263SQVAKRQ1  [VAK0015A-MFG]

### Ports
48V/12V_P (in), CLK_EPB_WSS (in), Cutoff_EPB (in), DRVOFF_EPB (in), IN1_EPB (in), IN2_EPB (in), Isense_EPB (out), nFAULT_EPB (out), nSCS_EPB (in), nSCS_WSS (in), OUTA_EPB (out), OUTB_EPB (out), SDI_EPB_WSS (in), SDO_EPB_WSS (out), WSN (out), WSP (out), WSSO (out)

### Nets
3.3V: C91.2 C98.2 D12.1(K) R91.2 R92.1 U6.6(VIO) U7.11(VDD)
5V: C92.2 U6.5(VCC5)
12V: C89.2 U6.1(VBAT)
48V/12V_BDC: C96.2 C97.1 Q11.1(S) Q11.2(S) Q11.3(S) R87.1 U7.4(VM)
48V/12V_P: Q11.5(D) ; port 48V/12V_P
GND: C88.1 C89.1 C90.1 C91.1 C92.1 C93.1 C94.1 C95.2 C96.1 C97.2 C98.1 C99.1 C100.1 D5.3(GND) R95.1 U6.4(GND) U6.13(EP) U7.6(GND)
CLKEPB: U6.11(SCLK) U7.13(SCLK) ; port CLK_EPB_WSS
Cutoff_EPB: R85.1 ; port Cutoff_EPB
DRVOFF_EPB: R90.1 ; port DRVOFF_EPB
IN1_EPB: R94.1 ; port IN1_EPB
IN2_EPB: R93.1 ; port IN2_EPB
Isense_EPB: C100.2 D12.2(A) R95.2 U7.2(IPROPI) ; port Isense_EPB
nFAULT_EPB: C99.2 R92.2 U7.1(~{FAULT}) ; port nFAULT_EPB
nSCS_EPB: U7.12(~{SCS}) ; port nSCS_EPB
nSCS_WSS: U6.12(~{CS}) ; port nSCS_WSS
OUTA_EPB: U7.7(OUT1) ; port OUTA_EPB
OUTB_EPB: U7.5(OUT2) ; port OUTB_EPB
SDIEPB: U6.10(SDI) U7.14(SDI) ; port SDI_EPB_WSS
SDOEPB: R89.1 R96.1 ; port SDO_EPB_WSS
WSN: C94.2 D5.1(1_IO) R88.2 ; port WSN
WSP: C90.2 D5.2(2_IO) R86.2 ; port WSP
WSSO: C88.2 R84.2 ; port WSSO
NetC93_2: C93.2 R88.1 U6.3(WSSR)
NetC95_1: C95.1 U6.7(V1P5)
NetQ11_4: Q11.4(G) R85.2 R87.2
NetR84_1: R84.1 TP16.1 U6.8(WSSO)
NetR86_1: R86.1 U6.2(WSSP)
NetR89_2: R89.2 U6.9(SDO)
NetR90_2: R90.2 U7.8(DRVOFF)
NetR91_1: R91.1 U7.3(~{SLEEP})
NetR93_2: R93.2 U7.9(EN/IN1)
NetR94_2: R94.2 U7.10(PH/IN2)
NetR96_2: R96.2 U7.15(SDO)

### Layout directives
net class 48V: 48V/12V_BDC, Cutoff_EPB, OUTA_EPB, OUTB_EPB

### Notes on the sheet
- EPB & WSS
- (near R84) Place close to DSP
- Both devices controlled with same signal group?
- Need BUS cutoff?
- (near U7) ECAP is too big?
- Place close to WSS001
- Place near external PCB connections
- Place close to DSP

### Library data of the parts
C88 C90 C94 = CMP-0860997-1: as C35 on sheet PMIC
C89 C91-C93 C98-C100 = CMP-0006356-2: as C101 on sheet CAN
C95 = CMP-0007095-1: CAP, CERM, 0.33 uF, 50 V, +/- 10%, X7R, AEC-Q200 Grade 1, 0603; Manufacturer: TDK; TaMin_C: -55°C; ESR_ohm: 15.84m; Polarized: N; SizeAreaWB_mm2: 4.68; Value1: 0.01584 ohm; U/M: EA; Value: 0.33uF; TaMax_C: 125°C; SizeZ_mm: 1; SizeX_mm: 1.6; SizeY_mm: 0.8; SizeArea_mm2: 1.28; AEC Qualified: Y; IRMS_A: 1.3135A; AEC Category: Q200
C96 = CMP-0009182-2: CAP, CERM, 4.7 uF, 100 V, +/- 10%, X7S, 1210; Manufacturer: MuRata; TaMin_C: -55°C; Polarized: N; SizeAreaWB_mm2: 14.7; Value1: Unknown; U/M: EA; Value: 4.7uF; TaMax_C: 125°C; SizeZ_mm: 2.2; SizeX_mm: 3.2; SizeY_mm: 2.5; Cap_Case: 1210; SizeArea_mm2: 8; Cap_F: 4.7µF; AEC Category: Q200
C97 = CMP-0860999-1: as C102 on sheet CAN
D5 = CMP-0125988-1: Automotive, dual, 3-pF, ±24-V, ±30-kV ESD protection diode for in-vehicle networks 3-SOT-23 -55 to 150; Manufacturer: Texas Instruments; AEC Qualified: Yes; SizeZ_mm: 1.12mm; VRWM: 24V; Ipp: 5.7A; Ppk: 210W; AEC Grade: Grade 0; Breakdown Voltage: 25.5V; Cap_F: 3pF; Clamping Voltage: 37V; Direction: Bidirectional; Number Of Channels: 2; Standoff Height: 0.01mm; TaMax_C: +150°C; TaMin_C: -55°C
D12 = CMP-0080760-2: Diode, Schottky, 100 V, 0.15 A, AEC-Q101, SOD-123; Manufacturer: Vishay-Semiconductor; SizeArea_mm2: 6.545; Io_A: 150mA; Vr_V: 100V; Value: 100V; SizeAreaWB_mm2: 13.095; AEC Qualified: Y; Vf_V: 1V; SizeZ_mm: 1.35; Value1: 0.15A; TJmax_C: 125°C; SizeY_mm: 1.7; SizeX_mm: 3.85; AEC Category: Q101
Q11 = CMP-0086155-1: MOSFET, N-CH, 80 V, 60 A, AEC-Q101, PowerPAK_SO-8L; Alternate Manufacturer: None; Manufacturer: Vishay-Siliconix; SizeZ_mm: 1.14; SizeArea_mm2: 31.5495; ChMode: Enhancement; AEC Category: Q101; AEC Qualified: Y; Vgs_V: 20V; SizeAreaWB_mm2: 58.1095; Value2: 36 nC; Value1: ? ohm; QgTyp_nC: 36; SizeY_mm: 5.13; SizeX_mm: 6.15; ChType: N
R84 = CMP-0025951-3: as R43 on sheet PMIC
R85 R86 R88 R90 = CMP-0025963-3: RES, 10.0, 1%, 0.063 W, AEC-Q200 Grade 0, 0402; Manufacturer: Vishay-Dale; Power_W: 63mW; TempCo: 100 ppm/C; Value_Code: 10R0; Value: 10.0; EIA_Code: E96; Res_ohm: 10; SizeX_mm: 1; SizeY_mm: 0.5; SizeZ_mm: 0.6; Value2: 0.063W; AEC Qualified: Y; VDC_V: 50V; AEC Category: Q200; AEC Grade: 0
R87 = CMP-0025950-3: as R120 on sheet Sensor
R89 R93 R94 R96 = CMP-0026908-3: as R101 on sheet CAN
R91 R92 = CMP-0025958-3: as R102 on sheet CAN
R95 = CMP-0026071-3: as R119 on sheet Sensor
TP16 = CMP-0055152-2: Test Point, Miniature, SMT; Manufacturer: Keystone Electronics; CT: TRUE; Green_Lifecycle: Active; Green_REACh: Passed; CNHeader: FALSE
U6 = CMP-0123269-1: Manufacturer: Texas Instruments; SizeZ_mm: 0.8mm; Standoff Height: 0mm
U7 = CMP-0121932-1: Automotive 65-V H-Bridge Driver with Integrated Current Sense and Diagnostics; Manufacturer: Texas Instruments; SizeZ_mm: 1mm; AEC Qualified: Yes; AEC Grade: Grade 1; Max Supply Voltage: 65V; Min Supply Voltage: 3V; Motor Type: Brushed; Nominal Supply Current: 3mA; Number Of Outputs: 2; Standoff Height: 0mm; Switching Frequency: 0-100kHz; TaMax_C: +125°C; TaMin_C: -40°C; TJmax_C: +150°C

## Sheet BLDC.SchDoc: BLDC
size 431 x 279 mm; Date: Not shown in title block; ApprovedBy: Not shown in title block; CheckedBy: Not shown in title block; Author: Not shown in title block; CompanyName: Not shown in title block; DrawnBy: Hely Zhang; Engineer: Not shown in title block; Organization: Not shown in title block; Address1: Not shown in title block; Address2: Not shown in title block; Address3: Not shown in title block; Address4: Not shown in title block; DocumentNumber: 1; Revision: Use project parameter SCH_Rev; SheetNumber: 6; SheetTotal: 15; PageSetup: Record=PageOptions¦CenterHorizontal=True¦CenterVertical=True¦PrintScale=1.00¦XCorrection=1.00¦YCorrection=1.00¦PrintKind=0¦BorderSize=5000000¦LeftOffset=0¦BottomOffset=0¦Orientation=2¦PaperLength=1000¦PaperWidth=1000¦Scale=100¦PaperSource=15¦PrintQuality=600¦MediaType=1¦DitherType=10¦PaperKind=Letter¦PrintScaleMode=1
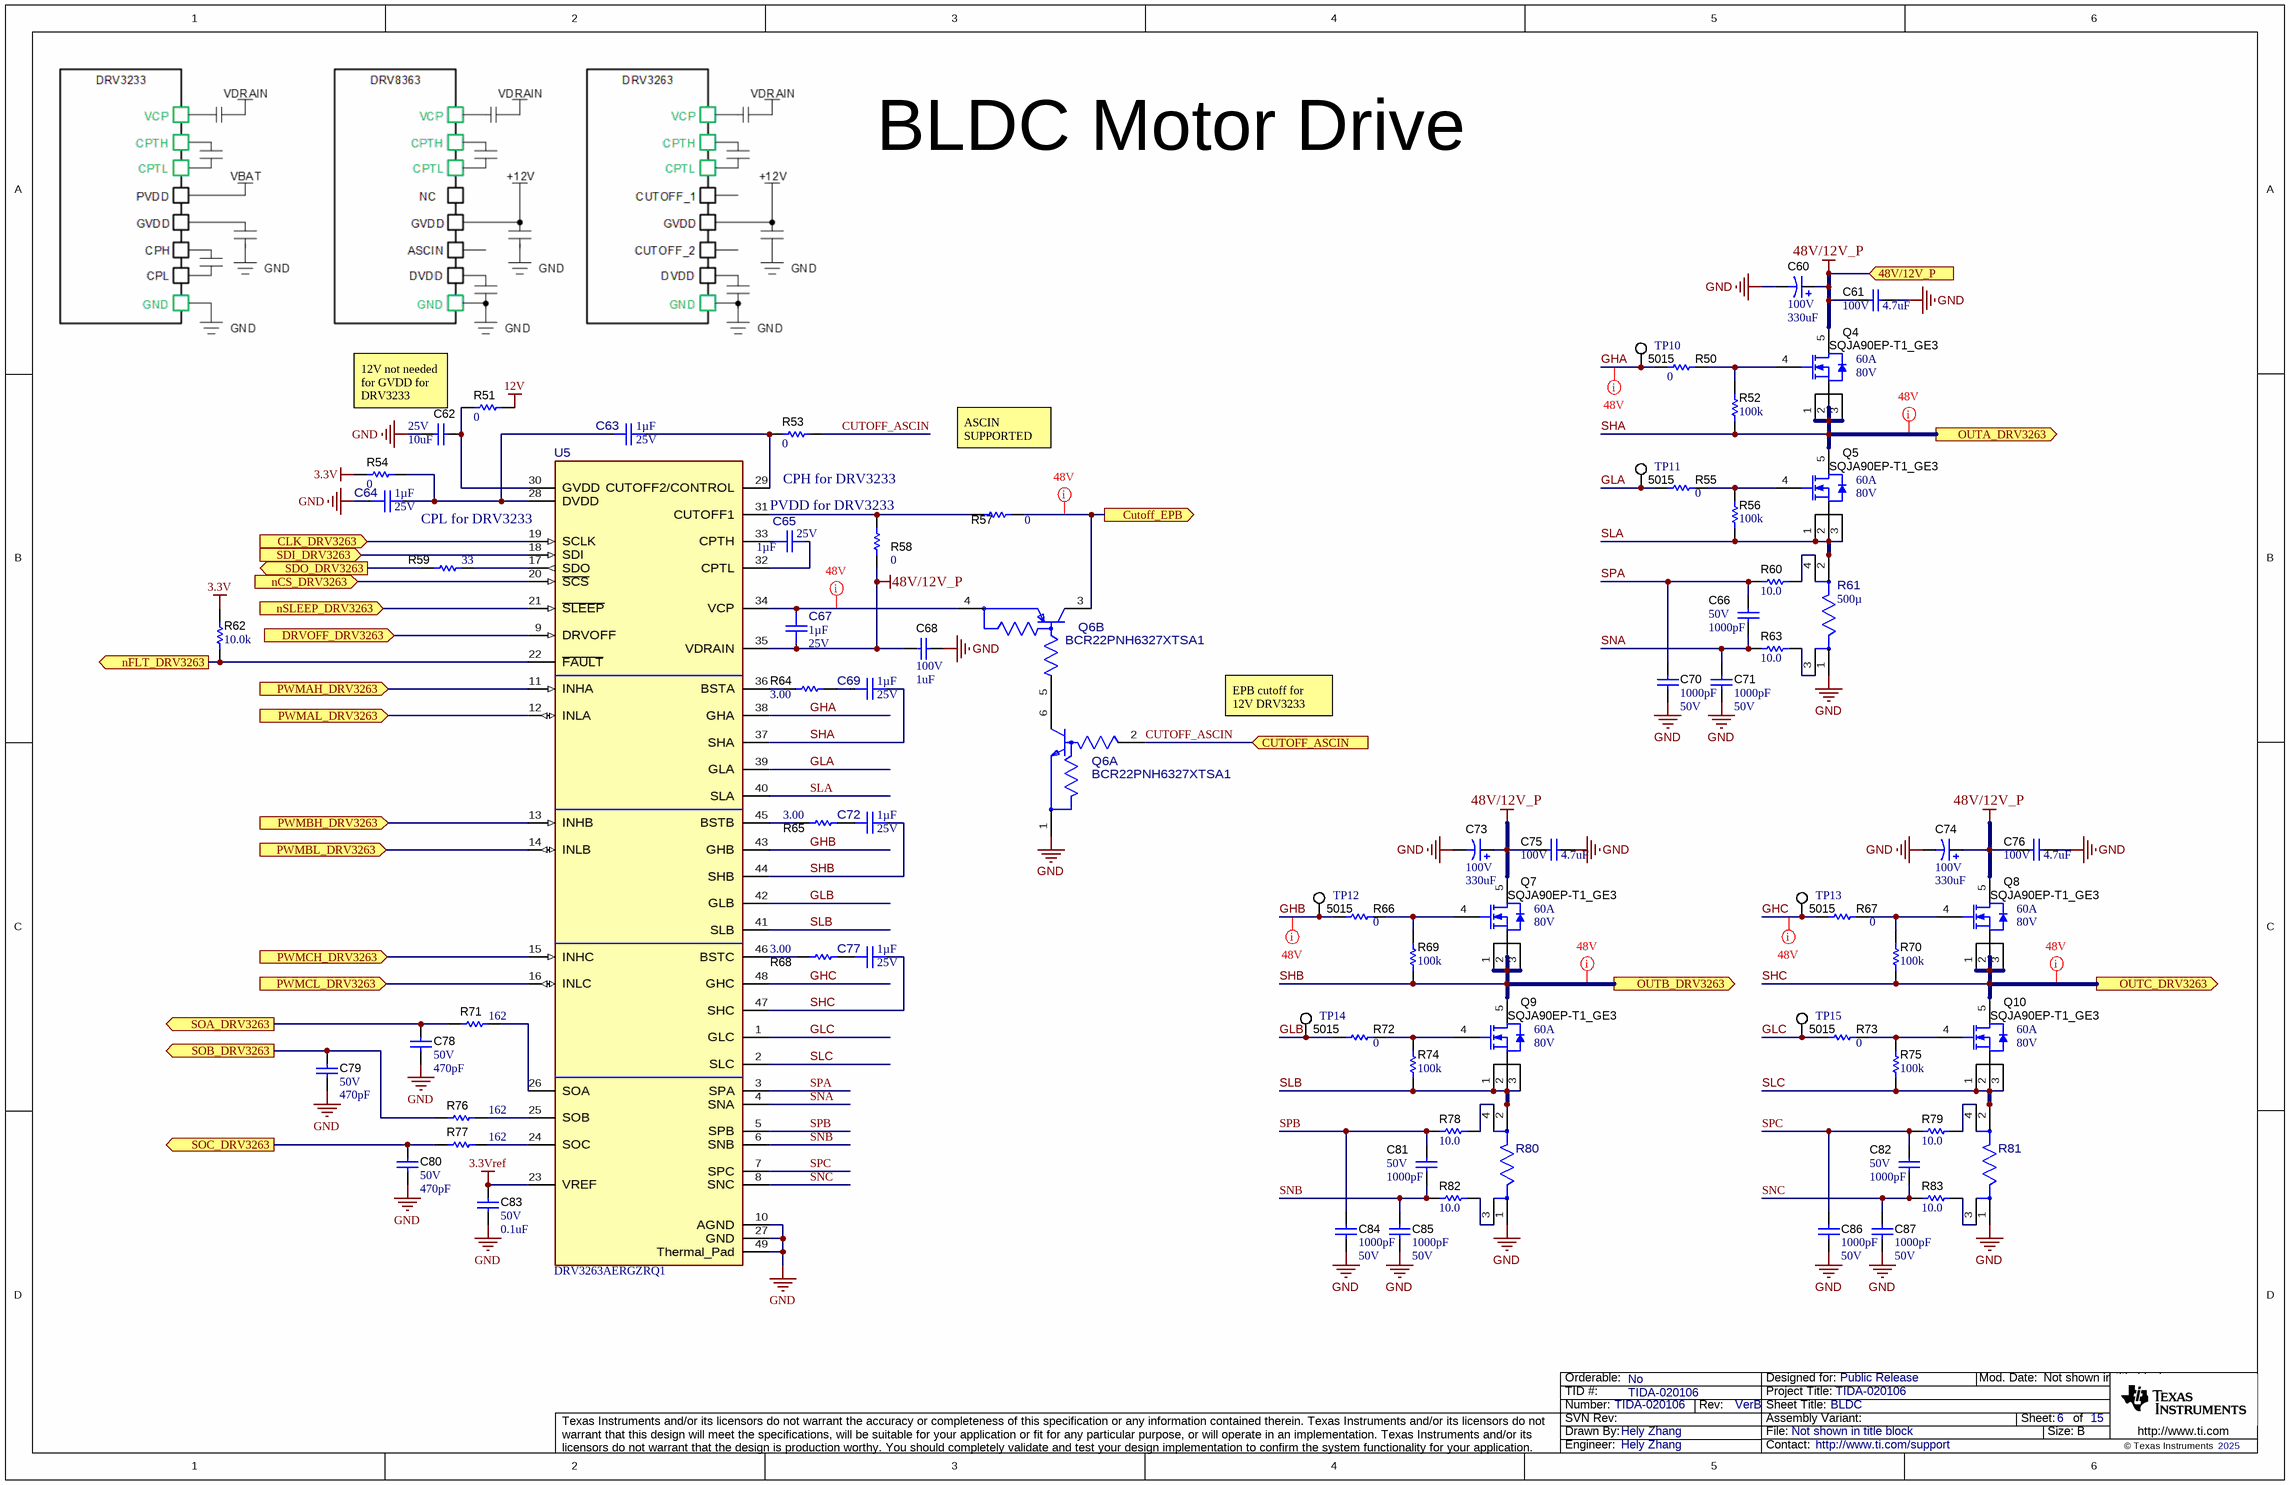
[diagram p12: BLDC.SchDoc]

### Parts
C60  VDC_V: 100V  ValueDisplayed: 330uF  [CAPSMT_62_MN0]  (hidden comment: EMVE101GTR331MMN0S)
C61  VDC_V: 100V  ValueDisplayed: 4.7uF  [1210_220]  (hidden comment: GRM32DC72A475KE01L)
C62  VDC_V: 25V  ValueDisplayed: 10uF  [0603]  (hidden comment: RC0603FR-07200RL)
C63  Cap_F: 1µF  VDC_V: 25V  [FP-AGC0603X7R250-105KXP_0603-MFG]  (hidden comment: AGC0603X7R250-105KXP)
C64  Cap_F: 1µF  VDC_V: 25V  [FP-AGC0603X7R250-105KXP_0603-MFG]  (hidden comment: AGC0603X7R250-105KXP)
C65  Cap_F: 1µF  VDC_V: 25V  [FP-AGC0603X7R250-105KXP_0603-MFG]  (hidden comment: AGC0603X7R250-105KXP)
C66  ValueDisplayed: 1000pF  VDC_V: 50V  [0402]  (hidden comment: CGA2B2X8R1H102K050BA)
C67  Cap_F: 1µF  VDC_V: 25V  [FP-AGC0603X7R250-105KXP_0603-MFG]  (hidden comment: AGC0603X7R250-105KXP)
C68  VDC_V: 100V  ValueDisplayed: 1uF  [1206_180]  (hidden comment: GCM31CR72A105KA03)
C69  Cap_F: 1µF  VDC_V: 25V  [FP-AGC0603X7R250-105KXP_0603-MFG]  (hidden comment: AGC0603X7R250-105KXP)
C70  ValueDisplayed: 1000pF  VDC_V: 50V  [0402]  (hidden comment: CGA2B2X8R1H102K050BA)
C71  ValueDisplayed: 1000pF  VDC_V: 50V  [0402]  (hidden comment: CGA2B2X8R1H102K050BA)
C72  Cap_F: 1µF  VDC_V: 25V  [FP-AGC0603X7R250-105KXP_0603-MFG]  (hidden comment: AGC0603X7R250-105KXP)
C73  VDC_V: 100V  ValueDisplayed: 330uF  [CAPSMT_62_MN0]  (hidden comment: EMVE101GTR331MMN0S)
C74  VDC_V: 100V  ValueDisplayed: 330uF  [CAPSMT_62_MN0]  (hidden comment: EMVE101GTR331MMN0S)
C75  VDC_V: 100V  ValueDisplayed: 4.7uF  [1210_220]  (hidden comment: GRM32DC72A475KE01L)
C76  VDC_V: 100V  ValueDisplayed: 4.7uF  [1210_220]  (hidden comment: GRM32DC72A475KE01L)
C77  Cap_F: 1µF  VDC_V: 25V  [FP-AGC0603X7R250-105KXP_0603-MFG]  (hidden comment: AGC0603X7R250-105KXP)
C78  VDC_V: 50V  ValueDisplayed: 470pF  [0402]  (hidden comment: GRT155R71H471KE01D)
C79  VDC_V: 50V  ValueDisplayed: 470pF  [0402]  (hidden comment: GRT155R71H471KE01D)
C80  VDC_V: 50V  ValueDisplayed: 470pF  [0402]  (hidden comment: GRT155R71H471KE01D)
C81  ValueDisplayed: 1000pF  VDC_V: 50V  [0402]  (hidden comment: CGA2B2X8R1H102K050BA)
C82  ValueDisplayed: 1000pF  VDC_V: 50V  [0402]  (hidden comment: CGA2B2X8R1H102K050BA)
C83  VDC_V: 50V  ValueDisplayed: 0.1uF  [0402]  (hidden comment: GCM155R71H104KE02D)
C84  ValueDisplayed: 1000pF  VDC_V: 50V  [0402]  (hidden comment: CGA2B2X8R1H102K050BA)
C85  ValueDisplayed: 1000pF  VDC_V: 50V  [0402]  (hidden comment: CGA2B2X8R1H102K050BA)
C86  ValueDisplayed: 1000pF  VDC_V: 50V  [0402]  (hidden comment: CGA2B2X8R1H102K050BA)
C87  ValueDisplayed: 1000pF  VDC_V: 50V  [0402]  (hidden comment: CGA2B2X8R1H102K050BA)
Q4  SQJA90EP-T1_GE3  value 80V  IdsMax_A: 60A  [PowerPAK_SO-8L]
Q5  SQJA90EP-T1_GE3  value 80V  IdsMax_A: 60A  [PowerPAK_SO-8L]
Q6  BCR22PNH6327XTSA1  [FP-BCR22PNH6327XTSA1_SOT363-MFG]  (parts A,B of 2)
Q7  SQJA90EP-T1_GE3  value 80V  IdsMax_A: 60A  [PowerPAK_SO-8L]
Q8  SQJA90EP-T1_GE3  value 80V  IdsMax_A: 60A  [PowerPAK_SO-8L]
Q9  SQJA90EP-T1_GE3  value 80V  IdsMax_A: 60A  [PowerPAK_SO-8L]
Q10  SQJA90EP-T1_GE3  value 80V  IdsMax_A: 60A  [PowerPAK_SO-8L]
R50  ValueDisplayed: 0  [0402]  (hidden comment: CRCW04020000Z0ED)
R51  ValueDisplayed: 0  [0402]  (hidden comment: CRCW04020000Z0ED)
R52  ValueDisplayed: 100k  [0402]  (hidden comment: CRCW0402100KFKED)
R53  ValueDisplayed: 0  [0402]  (hidden comment: CRCW04020000Z0ED)
R54  ValueDisplayed: 0  [0402]  (hidden comment: CRCW04020000Z0ED)
R55  ValueDisplayed: 0  [0402]  (hidden comment: CRCW04020000Z0ED)
R56  ValueDisplayed: 100k  [0402]  (hidden comment: CRCW0402100KFKED)
R57  ValueDisplayed: 0  [0402]  (hidden comment: CRCW04020000Z0ED)
R58  ValueDisplayed: 0  [0402]  (hidden comment: CRCW04020000Z0ED)
R59  ValueDisplayed: 33  [0402]  (hidden comment: CRCW040233R0JNED)
R60  ValueDisplayed: 10.0  [0402]  (hidden comment: CRCW040210R0FKED)
R61  Res_ohm: 500µ  [FP-BVN-Z-R0005-1.0_1612-MFG]  (hidden comment: BVN-Z-R0005-1.0)
R62  ValueDisplayed: 10.0k  [0402]  (hidden comment: CRCW040210K0FKED)
R63  ValueDisplayed: 10.0  [0402]  (hidden comment: CRCW040210R0FKED)
R64  ValueDisplayed: 3.00  [0603]  (hidden comment: KTR03EZPF3R00)
R65  ValueDisplayed: 3.00  [0603]  (hidden comment: KTR03EZPF3R00)
R66  ValueDisplayed: 0  [0402]  (hidden comment: CRCW04020000Z0ED)
R67  ValueDisplayed: 0  [0402]  (hidden comment: CRCW04020000Z0ED)
R68  ValueDisplayed: 3.00  [0603]  (hidden comment: KTR03EZPF3R00)
R69  ValueDisplayed: 100k  [0402]  (hidden comment: CRCW0402100KFKED)
R70  ValueDisplayed: 100k  [0402]  (hidden comment: CRCW0402100KFKED)
R71  ValueDisplayed: 162  [0402]  (hidden comment: CRCW0402162RFKED)
R72  ValueDisplayed: 0  [0402]  (hidden comment: CRCW04020000Z0ED)
R73  ValueDisplayed: 0  [0402]  (hidden comment: CRCW04020000Z0ED)
R74  ValueDisplayed: 100k  [0402]  (hidden comment: CRCW0402100KFKED)
R75  ValueDisplayed: 100k  [0402]  (hidden comment: CRCW0402100KFKED)
R76  ValueDisplayed: 162  [0402]  (hidden comment: CRCW0402162RFKED)
R77  ValueDisplayed: 162  [0402]  (hidden comment: CRCW0402162RFKED)
R78  ValueDisplayed: 10.0  [0402]  (hidden comment: CRCW040210R0FKED)
R79  ValueDisplayed: 10.0  [0402]  (hidden comment: CRCW040210R0FKED)
R80  BVN-Z-R0005-1.0  [FP-BVN-Z-R0005-1.0_1612-MFG]  (value not drawn)
R81  BVN-Z-R0005-1.0  [FP-BVN-Z-R0005-1.0_1612-MFG]  (value not drawn)
R82  ValueDisplayed: 10.0  [0402]  (hidden comment: CRCW040210R0FKED)
R83  ValueDisplayed: 10.0  [0402]  (hidden comment: CRCW040210R0FKED)
TP10  5015  [Testpoint_Keystone_Miniature]
TP11  5015  [Testpoint_Keystone_Miniature]
TP12  5015  [Testpoint_Keystone_Miniature]
TP13  5015  [Testpoint_Keystone_Miniature]
TP14  5015  [Testpoint_Keystone_Miniature]
TP15  5015  [Testpoint_Keystone_Miniature]
U5  DRV3263AERGZRQ1  [RGZ0048N-MFG]

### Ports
48V/12V_P (in), CLK_DRV3263 (in), CUTOFF_ASCIN (in), Cutoff_EPB (out), DRVOFF_DRV3263 (in), nCS_DRV3263 (in), nFLT_DRV3263 (out), nSLEEP_DRV3263 (in), OUTA_DRV3263 (out), OUTB_DRV3263 (out), OUTC_DRV3263 (out), PWMAH_DRV3263 (in), PWMAL_DRV3263 (in), PWMBH_DRV3263 (in), PWMBL_DRV3263 (in), PWMCH_DRV3263 (in), PWMCL_DRV3263 (in), SDI_DRV3263 (in), SDO_DRV3263 (out), SOA_DRV3263 (out), SOB_DRV3263 (out), SOC_DRV3263 (out)

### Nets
3.3V: R54.1 R62.2
3.3Vref: C83.1 U5.23(VREF)
12V: R51.2
48V/12V_P: C60.1(+) C61.1 C67.2 C68.1 C73.1(+) C74.1(+) C75.1 C76.1 Q4.5(D) Q7.5(D) Q8.5(D) R58.2 U5.35(VDRAIN) ; port 48V/12V_P
GND: C60.2(-) C61.2 C62.2 C64.1 C68.2 C70.2 C71.2 C73.2(-) C74.2(-) C75.2 C76.2 C78.2 C79.2 C80.2 C83.2 C84.2 C85.2 C86.2 C87.2 Q6.1(E1) R61.1 R80.1 R81.1 U5.10(AGND) U5.27(GND) U5.49(Thermal_Pad)
CLK_DRV3263: U5.19(SCLK) ; port CLK_DRV3263
CUTOFF_ASCIN: Q6.2(B1) R53.1 ; port CUTOFF_ASCIN
Cutoff_EPB: Q6.3(C2) R57.1 ; port Cutoff_EPB
DRVOFF_DRV3263: U5.9(DRVOFF) ; port DRVOFF_DRV3263
GHA: R50.2 TP10.1 U5.38(GHA)
GHB: R66.2 TP12.1 U5.43(GHB)
GHC: R67.2 TP13.1 U5.48(GHC)
GLA: R55.2 TP11.1 U5.39(GLA)
GLB: R72.2 TP14.1 U5.42(GLB)
GLC: R73.2 TP15.1 U5.1(GLC)
nCS_DRV3263: U5.20(~{SCS}) ; port nCS_DRV3263
nFLT_DRV3263: R62.1 U5.22(~{FAULT}) ; port nFLT_DRV3263
nSLEEP_DRV3263: U5.21(~{SLEEP}) ; port nSLEEP_DRV3263
PWMAH: U5.11(INHA) ; port PWMAH_DRV3263
PWMAL: U5.12(INLA) ; port PWMAL_DRV3263
PWMBH: U5.13(INHB) ; port PWMBH_DRV3263
PWMBL: U5.14(INLB) ; port PWMBL_DRV3263
PWMCH: U5.15(INHC) ; port PWMCH_DRV3263
PWMCL: U5.16(INLC) ; port PWMCL_DRV3263
SDI_DRV3263: U5.18(SDI) ; port SDI_DRV3263
SDO_DRV3263: R59.1 ; port SDO_DRV3263
SHA: C69.1 Q4.1(S) Q4.2(S) Q4.3(S) Q5.5(D) R52.1 U5.37(SHA) ; port OUTA_DRV3263
SHB: C72.1 Q7.1(S) Q7.2(S) Q7.3(S) Q9.5(D) R69.1 U5.44(SHB) ; port OUTB_DRV3263
SHC: C77.1 Q8.1(S) Q8.2(S) Q8.3(S) Q10.5(D) R70.1 U5.47(SHC) ; port OUTC_DRV3263
SLA: Q5.1(S) Q5.2(S) Q5.3(S) R56.1 R61.2 U5.40(SLA)
SLB: Q9.1(S) Q9.2(S) Q9.3(S) R74.1 R80.2 U5.41(SLB)
SLC: Q10.1(S) Q10.2(S) Q10.3(S) R75.1 R81.2 U5.2(SLC)
SNA: C66.2 C71.1 R63.1 U5.4(SNA)
SNB: C81.2 C85.1 R82.1 U5.6(SNB)
SNC: C82.2 C87.1 R83.1 U5.8(SNC)
SOA_DRV3263: C78.1 R71.1 ; port SOA_DRV3263
SOB_DRV3263: C79.1 R76.1 ; port SOB_DRV3263
SOC_DRV3263: C80.1 R77.1 ; port SOC_DRV3263
SPA: C66.1 C70.1 R60.1 U5.3(SPA)
SPB: C81.1 C84.1 R78.1 U5.5(SPB)
SPC: C82.1 C86.1 R79.1 U5.7(SPC)
NetC62_1: C62.1 R51.1 U5.30(GVDD)
NetC63_1: C63.1 R53.2 U5.29(CUTOFF2/CONTROL)
NetC63_2: C63.2 C64.2 R54.2 U5.28(DVDD)
NetC65_1: C65.1 U5.33(CPTH)
NetC65_2: C65.2 U5.32(CPTL)
NetC67_1: C67.1 Q6.4(E2) U5.34(VCP)
NetC69_2: C69.2 R64.2
NetC72_2: C72.2 R65.2
NetC77_2: C77.2 R68.2
NetQ4_4: Q4.4(G) R50.1 R52.2
NetQ5_4: Q5.4(G) R55.1 R56.2
NetQ6_5: Q6.5(B2) Q6.6(C1)
NetQ7_4: Q7.4(G) R66.1 R69.2
NetQ8_4: Q8.4(G) R67.1 R70.2
NetQ9_4: Q9.4(G) R72.1 R74.2
NetQ10_4: Q10.4(G) R73.1 R75.2
NetR57_2: R57.2 R58.1 U5.31(CUTOFF1)
NetR59_2: R59.2 U5.17(SDO)
NetR60_2: R60.2 R61.4
NetR61_3: R61.3 R63.2
NetR64_1: R64.1 U5.36(BSTA)
NetR65_1: R65.1 U5.45(BSTB)
NetR68_1: R68.1 U5.46(BSTC)
NetR71_2: R71.2 U5.26(SOA)
NetR76_2: R76.2 U5.25(SOB)
NetR77_2: R77.2 U5.24(SOC)
NetR78_2: R78.2 R80.4
NetR79_2: R79.2 R81.4
NetR80_3: R80.3 R82.2
NetR81_3: R81.3 R83.2

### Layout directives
net class 48V: Cutoff_EPB, GHA, GHB, GHC, NetC67_1, SHA, SHB, SHC

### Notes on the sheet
- BLDC Motor Drive
- 12V not needed for GVDD for DRV3233
- CPH for DRV3233
- ASCIN SUPPORTED
- CPL for DRV3233
- (near R58) PVDD for DRV3233
- EPB cutoff for 12V DRV3233

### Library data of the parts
C60 C73 C74 = CMP-0011277-1: CAP, AL, 330 uF, 100 V, +/- 20%, SMD; Manufacturer: Chemi-Con; TaMin_C: -40°C; Polarized: Y; SizeAreaWB_mm2: 441; Value1: Unknown; U/M: EA; Value: 330uF; TaMax_C: 105°C; SizeZ_mm: 21.5; SizeX_mm: 19; Cap_Case: MN0; SizeArea_mm2: 361; CompType: Capacitor; Cap_F: 330µF; IRMS_A: 980mA; AEC Category: Q200
C61 C75 C76 = CMP-0009182-2: as C96 on sheet EPB
C62 = CMP-0007007-3: CAP, CERM, 10 uF, 25 V, +/- 20%, X5R, 0603; Manufacturer: TDK; PartNumber: C1608X5R1E106M080AC; TaMin_C: -55°C; ESR_ohm: 4.639m; Polarized: N; SizeAreaWB_mm2: 4.68; Value1: 0.004639 ohm; U/M: EA; Value: 10uF; TaMax_C: 85°C; SizeZ_mm: 1; SizeX_mm: 1.6; SizeY_mm: 0.8; SizeArea_mm2: 1.28; Cap_F: 10µF; IRMS_A: 2.4141A; AEC Category: Q200
C63-C65 C67 C69 C72 C77 = CMP-0123897-1: Auto Grade Capacitor, 0603, X7R, 25V, 1uF, ±10%; Manufacturer: Venkel; AEC Grade: Grade 1; AEC Qualified: Yes; SizeZ_mm: 0.95mm; TempCo: 15%; Value: 1µF
C66 C70 C71 C81 C82 C84-C87 = CMP-0860997-1: as C35 on sheet PMIC
C68 = CMP-0008815-2: CAP, CERM, 1 uF, 100 V, +/- 10%, X7R, AEC-Q200 Grade 1, 1206; Manufacturer: MuRata; TaMin_C: -55°C; Polarized: N; SizeAreaWB_mm2: 10.92; Value1: Unknown; U/M: EA; Value: 1uF; TaMax_C: 125°C; SizeZ_mm: 1.8; SizeX_mm: 3.2; SizeY_mm: 1.6; Cap_Case: 1206; SizeArea_mm2: 5.12; AEC Qualified: Y; Cap_F: 1µF; AEC Grade: 1; AEC Category: Q200
C78-C80 = CMP-0860801-1: CAP, CERM, 470 pF, 50 V,+/- 10%, X7R, AEC-Q200 Grade 1, 0402; Manufacturer: MuRata; SizeArea_mm2: 0.5; Value: 470pF; SizeAreaWB_mm2: 3; AEC Qualified: Y; TaMax_C: 125°C; TaMin_C: -55°C; U/M: EA; SizeZ_mm: 0.6; AEC Grade: 1; AEC Category: Q200; Polarized: N
C83 = CMP-0006356-2: as C101 on sheet CAN
Q4 Q5 Q7-Q10 = CMP-0086155-1: as Q11 on sheet EPB
Q6 = CMP-0049400-1: Trans Digital BJT NPN/PNP 50V 100mA 250mW 6-Pin SOT-363 T/R; Manufacturer: Infineon; AEC Qualified: Yes; NPN: 1; SizeZ_mm: 1mm; Vcesat1_V: 300mV; AEC Grade: Grade 0; Hfe Min: 50; Hfe Testic: 5mA; Hfe Testvce: 5V; Number Of Elements: 2; TJmax_C: +150°C; Unity Gain Freq: 130MHz
R50 R51 R53-R55 R57 R58 R66 R67 R72 R73 = CMP-0026822-3: as R97-R99 on sheet CAN
R52 R56 R69 R70 R74 R75 = CMP-0025950-3: as R120 on sheet Sensor
R59 = CMP-0026908-3: as R101 on sheet CAN
R60 R63 R78 R79 R82 R83 = CMP-0025963-3: as R85 on sheet EPB
R61 = CMP-0126683-1: 0.5 mOhms ±1% 9W Chip Resistor Wide 1612 (3831 Metric), 1216 Current Sense, Moisture Resistant; Manufacturer: Isabellenhuette; AEC Grade: Grade 0; AEC Qualified: Yes; SizeZ_mm: 1.9mm; TempCo: 50ppm/°C; Value: 500µ
R62 = CMP-0025958-3: as R102 on sheet CAN
R64 R65 R68 = CMP-0078498-1: RES, 3.00, 1%, 0.1 W, AEC-Q200 Grade 0, 0603; Manufacturer: Rohm; Power_W: 100mW; TempCo: 100 ppm/C; Value_Code: 3R00; Value: 3.00; Res_ohm: 3; SizeX_mm: 1.6; SizeY_mm: 0.8; SizeZ_mm: 1; Value2: 0.1W; SizeArea_mm2: 1.28; AEC Qualified: Y; VDC_V: 350V; AEC Grade: 0; AEC Category: Q200
R71 R76 R77 = CMP-0026035-3: RES, 162, 1%, 0.063 W, AEC-Q200 Grade 0, 0402; Manufacturer: Vishay-Dale; Power_W: 63mW; TempCo: 100 ppm/C; Value_Code: 162R; Value: 162; EIA_Code: E96; SizeX_mm: 1; SizeY_mm: 0.5; SizeZ_mm: 0.6; Value2: 0.063W; AEC Qualified: Y; VDC_V: 50V; AEC Category: Q200; AEC Grade: 0
R80 R81 = CMP-0126683-1: 0.5 mOhms ±1% 9W Chip Resistor Wide 1612 (3831 Metric), 1216 Current Sense, Moisture Resistant; Manufacturer: Isabellenhuette; AEC Grade: Grade 0; AEC Qualified: Yes; Res_ohm: 500µ; SizeZ_mm: 1.9mm; TempCo: 50ppm/°C; Value: 500µ
TP10-TP15 = CMP-0055152-1: as TP17-TP19 on sheet CAN
U5 = CMP-0127481-1: Manufacturer: Texas Instruments; SizeZ_mm: 1mm; Standoff Height: 0mm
